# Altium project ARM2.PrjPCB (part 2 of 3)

## Sheet P07_DDR3_SDRAM.SchDoc
size A3
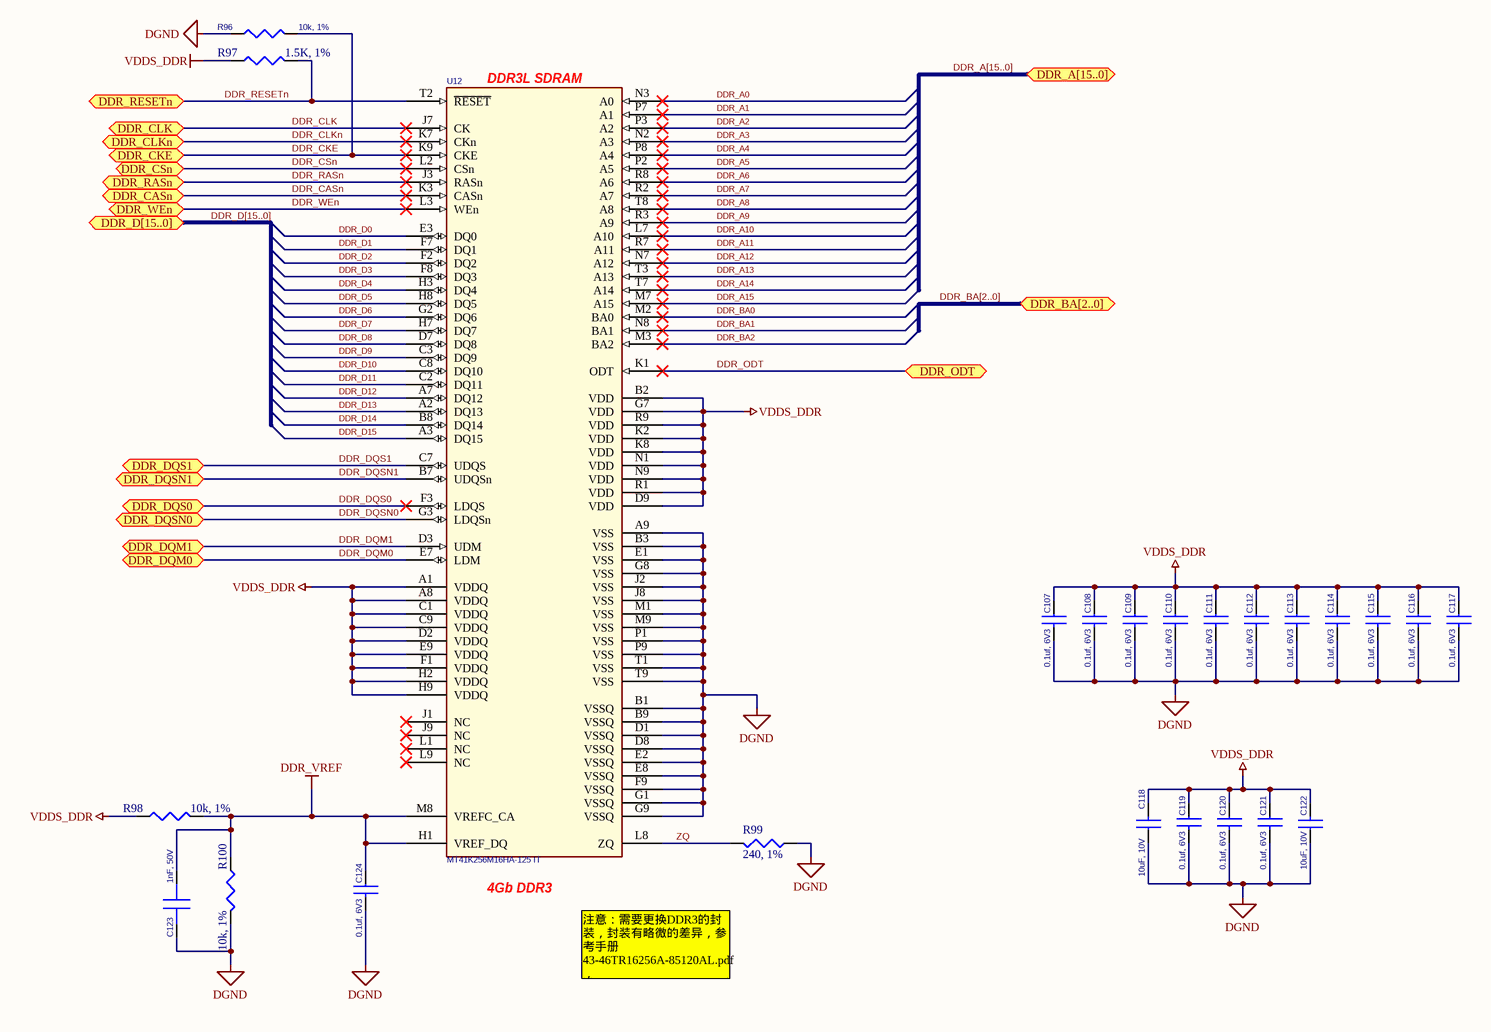
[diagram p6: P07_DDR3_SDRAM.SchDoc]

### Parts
C107  0.1uf, 6V3  [402]
C108  0.1uf, 6V3  [402]
C109  0.1uf, 6V3  [402]
C110  0.1uf, 6V3  [402]
C111  0.1uf, 6V3  [402]
C112  0.1uf, 6V3  [402]
C113  0.1uf, 6V3  [402]
C114  0.1uf, 6V3  [402]
C115  0.1uf, 6V3  [402]
C116  0.1uf, 6V3  [402]
C117  0.1uf, 6V3  [402]
C118  10uF, 10V  [805]
C119  0.1uf, 6V3  [402]
C120  0.1uf, 6V3  [402]
C121  0.1uf, 6V3  [402]
C122  10uF, 10V  [805]
C123  1nF, 50V  [402]
C124  0.1uf, 6V3  [402]
R96  10k, 1%  [R0402]
R97  1.5K, 1%  [R0402]
R98  10k, 1%  [R0402]
R99  240, 1%  [R0402]
R100  10k, 1%  [R0402]
U12  MT41K256M16HA-125 IT  [IS43TR16256A-15HBLI/MT41K256M16HA-125 IT_E TR]

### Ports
DDR_A[15..0], DDR_BA[2..0], DDR_CASn, DDR_CKE, DDR_CLK, DDR_CLKn, DDR_CSn, DDR_D[15..0], DDR_DQM0, DDR_DQM1, DDR_DQS0, DDR_DQS1, DDR_DQSN0, DDR_DQSN1, DDR_ODT, DDR_RASn, DDR_RESETn, DDR_WEn

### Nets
DDR_VREF: C123.1 C124.1 R98.2 R100.1 U12.H1(VREF_DQ) U12.M8(VREFC_CA)
DGND: C107.2 C108.2 C109.2 C110.2 C111.2 C112.2 C113.2 C114.2 C115.2 C116.2 C117.2 C118.1 C119.2 C120.2 C121.2 C122.1 C123.2 C124.2 R96.1 R99.1 R100.2 U12.A9(VSS) U12.B1(VSSQ) U12.B3(VSS) U12.B9(VSSQ) U12.D1(VSSQ) U12.D8(VSSQ) U12.E1(VSS) U12.E2(VSSQ) U12.E8(VSSQ) U12.F9(VSSQ) U12.G1(VSSQ) U12.G8(VSS) U12.G9(VSSQ) U12.J2(VSS) U12.J8(VSS) U12.M1(VSS) U12.M9(VSS) U12.P1(VSS) U12.P9(VSS) U12.T1(VSS) U12.T9(VSS)
VDDS_DDR: C107.1 C108.1 C109.1 C110.1 C111.1 C112.1 C113.1 C114.1 C115.1 C116.1 C117.1 C118.2 C119.1 C120.1 C121.1 C122.2 R97.1 R98.1 U12.A1(VDDQ) U12.A8(VDDQ) U12.B2(VDD) U12.C1(VDDQ) U12.C9(VDDQ) U12.D2(VDDQ) U12.D9(VDD) U12.E9(VDDQ) U12.F1(VDDQ) U12.G7(VDD) U12.H2(VDDQ) U12.H9(VDDQ) U12.K2(VDD) U12.K8(VDD) U12.N1(VDD) U12.N9(VDD) U12.R1(VDD) U12.R9(VDD)
DDR_A0: U12.N3(A0)
DDR_A1: U12.P7(A1)
DDR_A2: U12.P3(A2)
DDR_A3: U12.N2(A3)
DDR_A4: U12.P8(A4)
DDR_A5: U12.P2(A5)
DDR_A6: U12.R8(A6)
DDR_A7: U12.R2(A7)
DDR_A8: U12.T8(A8)
DDR_A9: U12.R3(A9)
DDR_A10: U12.L7(A10)
DDR_A11: U12.R7(A11)
DDR_A12: U12.N7(A12)
DDR_A13: U12.T3(A13)
DDR_A14: U12.T7(A14)
DDR_A15: U12.M7(A15)
DDR_BA0: U12.M2(BA0)
DDR_BA1: U12.N8(BA1)
DDR_BA2: U12.M3(BA2)
DDR_CASn: U12.K3(CASn) ; port DDR_CASn
DDR_CKE: R96.2 U12.K9(CKE) ; port DDR_CKE
DDR_CLK: U12.J7(CK) ; port DDR_CLK
DDR_CLKn: U12.K7(CKn) ; port DDR_CLKn
DDR_CSn: U12.L2(CSn) ; port DDR_CSn
DDR_D0: U12.E3(DQ0)
DDR_D1: U12.F7(DQ1)
DDR_D2: U12.F2(DQ2)
DDR_D3: U12.F8(DQ3)
DDR_D4: U12.H3(DQ4)
DDR_D5: U12.H8(DQ5)
DDR_D6: U12.G2(DQ6)
DDR_D7: U12.H7(DQ7)
DDR_D8: U12.D7(DQ8)
DDR_D9: U12.C3(DQ9)
DDR_D10: U12.C8(DQ10)
DDR_D11: U12.C2(DQ11)
DDR_D12: U12.A7(DQ12)
DDR_D13: U12.A2(DQ13)
DDR_D14: U12.B8(DQ14)
DDR_D15: U12.A3(DQ15)
DDR_DQM0: U12.E7(LDM) ; port DDR_DQM0
DDR_DQM1: U12.D3(UDM) ; port DDR_DQM1
DDR_DQS0: U12.F3(LDQS) ; port DDR_DQS0
DDR_DQS1: U12.C7(UDQS) ; port DDR_DQS1
DDR_DQSN0: U12.G3(LDQSn) ; port DDR_DQSN0
DDR_DQSN1: U12.B7(UDQSn) ; port DDR_DQSN1
DDR_ODT: U12.K1(ODT) ; port DDR_ODT
DDR_RASn: U12.J3(RASn) ; port DDR_RASn
DDR_RESETn: R97.2 U12.T2(~{RESET}) ; port DDR_RESETn
DDR_WEn: U12.L3(WEn) ; port DDR_WEn
ZQ: R99.2 U12.L8(ZQ)

Not connected (* = marked no-connect by the designer): U12 J1(NC)* J9(NC)* L1(NC)* L9(NC)*

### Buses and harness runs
bus DDR_A[15..0] = port DDR_A[15..0]
bus DDR_BA[2..0] = port DDR_BA[2..0]
bus DDR_D[15..0] = port DDR_D[15..0]

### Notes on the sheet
- (near U12) DDR3L SDRAM
- (near U12) 4Gb DDR3
- 注意：需要更换DDR3的封装，封装有略微的差异，参考手册43-46TR16256A-85120AL.pdf，
  96-ball FBGA (9mm*13mm)

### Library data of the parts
C107-C117 C119-C121 C124 = CAP_0.01uf_X7R_16V_10%_0402: CAP CER 0.1UF 6.3V 10% X5R 0402; Manufacturer: TDK Corporation; Manufacturer Part Number: C1005X5R0J104K050BA; Capacitance: 0.1µF; Tolerance: ?0%
C118 C122 = CAP_4.7uF_X5R_6.3V_10%_0603: CAP CER 10UF 10V Y5V 0805; Manufacturer: TDK Corporation; Manufacturer Part Number: C2012Y5V1A106Z; Capacitance: 10µF; Tolerance: -20%, +80%; Temperature Coefficient: Y5V (F)
C123 = CAP SMD: CAP CER 1000PF 16V 10% X7R 0402; Manufacturer: Yageo; Manufacturer Part Number: CC0402KRX7R7BB102; Tolerance: ?0%
R96 R98 R100 = RES_10K_1/16W_1%_0402: RES 10K OHM 1/16W 5% 0402 SMD; Manufacturer: Rohm Semiconductor; Manufacturer Part Number: MCR01MZPJ103; Power (Watts): 0.063W, 1/16W; Temperature Coefficient: ?00ppm/°C; Tolerance: ?%
R97 = RES_10K_1/16W_1%_0402: RES 1.50K OHM 1/16W 1% 0402 SMD; Manufacturer: Yageo; Manufacturer Part Number: RC0402FR-071K5L; Power (Watts): 0.063W, 1/16W; Temperature Coefficient: ?00ppm/°C; Tolerance: ?%
R99 = RES_10K_1/16W_1%_0402: RES 240 OHM 1/10W 5% 0402 SMD; Manufacturer: Yageo; Manufacturer Part Number: RC0402FR-07240RL; Resistance (Ohms): 240; Power (Watts): 0.063W, 1/16W; Temperature Coefficient: ?00ppm/°C; Tolerance: ?%
U12 = MT41K256M16HA: DDR2 SDRAM 2Gb (256Mx8); Manufacturer: ISSI; Manufacturer Part Number: IS43TR16256A-15HBLI; Lead Time: 0 weeks

## Sheet P08_NandFlash.SchDoc
size A4
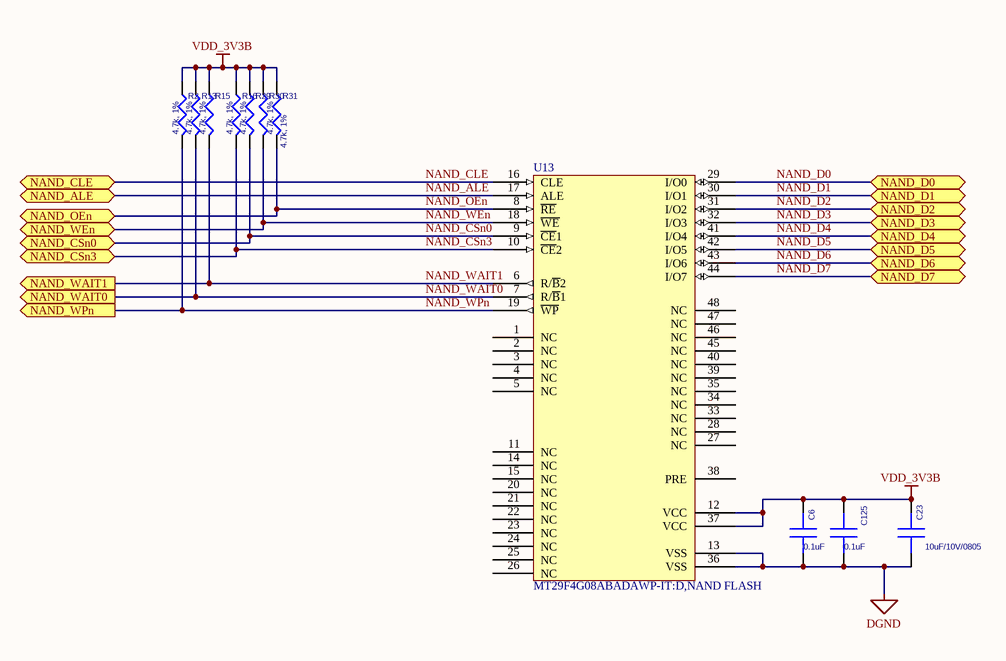
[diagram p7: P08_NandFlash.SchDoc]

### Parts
C6  0.1uF  [402]
C23  10uF/10V/0805  [3528T/CASE B]
C125  0.1uF  [402]
R2  4.7k, 1%  [R0402]
R13  4.7k, 1%  [R0402]
R15  4.7k, 1%  [R0402]
R16  4.7k, 1%  [R0402]
R29  4.7k, 1%  [R0402]
R30  4.7k, 1%  [R0402]
R31  4.7k, 1%  [R0402]
U13  MT29F4G08ABADAWP-IT:D,NAND FLASH  [MT29F4G08ABADAWP-ITD]

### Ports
NAND_ALE (bidir), NAND_CLE (bidir), NAND_CSn0 (bidir), NAND_CSn3 (bidir), NAND_D0 (bidir), NAND_D1 (bidir), NAND_D2 (bidir), NAND_D3 (bidir), NAND_D4 (bidir), NAND_D5 (bidir), NAND_D6 (bidir), NAND_D7 (bidir), NAND_OEn (bidir), NAND_WAIT0 (out), NAND_WAIT1 (out), NAND_WEn (bidir), NAND_WPn (out)

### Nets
DGND: C6.2 C23.2 C125.2 U13.13(VSS) U13.36(VSS)
VDD_3V3B: C6.1 C23.1 C125.1 R2.2(P2) R13.2(P2) R15.2(P2) R16.2(P2) R29.2(P2) R30.2(P2) R31.2(P2) U13.12(VCC) U13.37(VCC)
NAND_ALE: U13.17(ALE) ; port NAND_ALE
NAND_CLE: U13.16(CLE) ; port NAND_CLE
NAND_CSn0: R29.1(P1) U13.9(~{CE}1) ; port NAND_CSn0
NAND_CSn3: R16.1(P1) U13.10(~{CE}2) ; port NAND_CSn3
NAND_D0: U13.29(I/O0) ; port NAND_D0
NAND_D1: U13.30(I/O1) ; port NAND_D1
NAND_D2: U13.31(I/O2) ; port NAND_D2
NAND_D3: U13.32(I/O3) ; port NAND_D3
NAND_D4: U13.41(I/O4) ; port NAND_D4
NAND_D5: U13.42(I/O5) ; port NAND_D5
NAND_D6: U13.43(I/O6) ; port NAND_D6
NAND_D7: U13.44(I/O7) ; port NAND_D7
NAND_OEn: R31.1(P1) U13.8(~{RE}) ; port NAND_OEn
NAND_WAIT0: R13.1(P1) U13.7(R/~{B}1) ; port NAND_WAIT0
NAND_WAIT1: R15.1(P1) U13.6(R/~{B}2) ; port NAND_WAIT1
NAND_WEn: R30.1(P1) U13.18(~{WE}) ; port NAND_WEn
NAND_WPn: R2.1(P1) U13.19(~{WP}) ; port NAND_WPn

Not connected (* = marked no-connect by the designer): U13 1(NC) 2(NC) 3(NC) 4(NC) 5(NC) 11(NC) 14(NC) 15(NC) 20(NC) 21(NC) 22(NC) 23(NC) 24(NC) 25(NC) 26(NC) 27(NC) 28(NC) 33(NC) 34(NC) 35(NC) 38(PRE) 39(NC) 40(NC) 45(NC) 46(NC) 47(NC) 48(NC)

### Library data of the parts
C6 C23 C125 = CAP SMD: No Description
R2 R13 R15 R16 R29-R31 = RES SMD: RES 10K OHM 1/16W 5% 0402 SMD; Manufacturer: Rohm Semiconductor; Manufacturer Part Number: MCR01MZPJ103; Power (Watts): 0.063W, 1/16W; Temperature Coefficient: ?00ppm/°C; Tolerance: ?%
U13 = MT29F4G08ABADAWP-IT:D

## Sheet P09_Ethernet.SchDoc
size A2
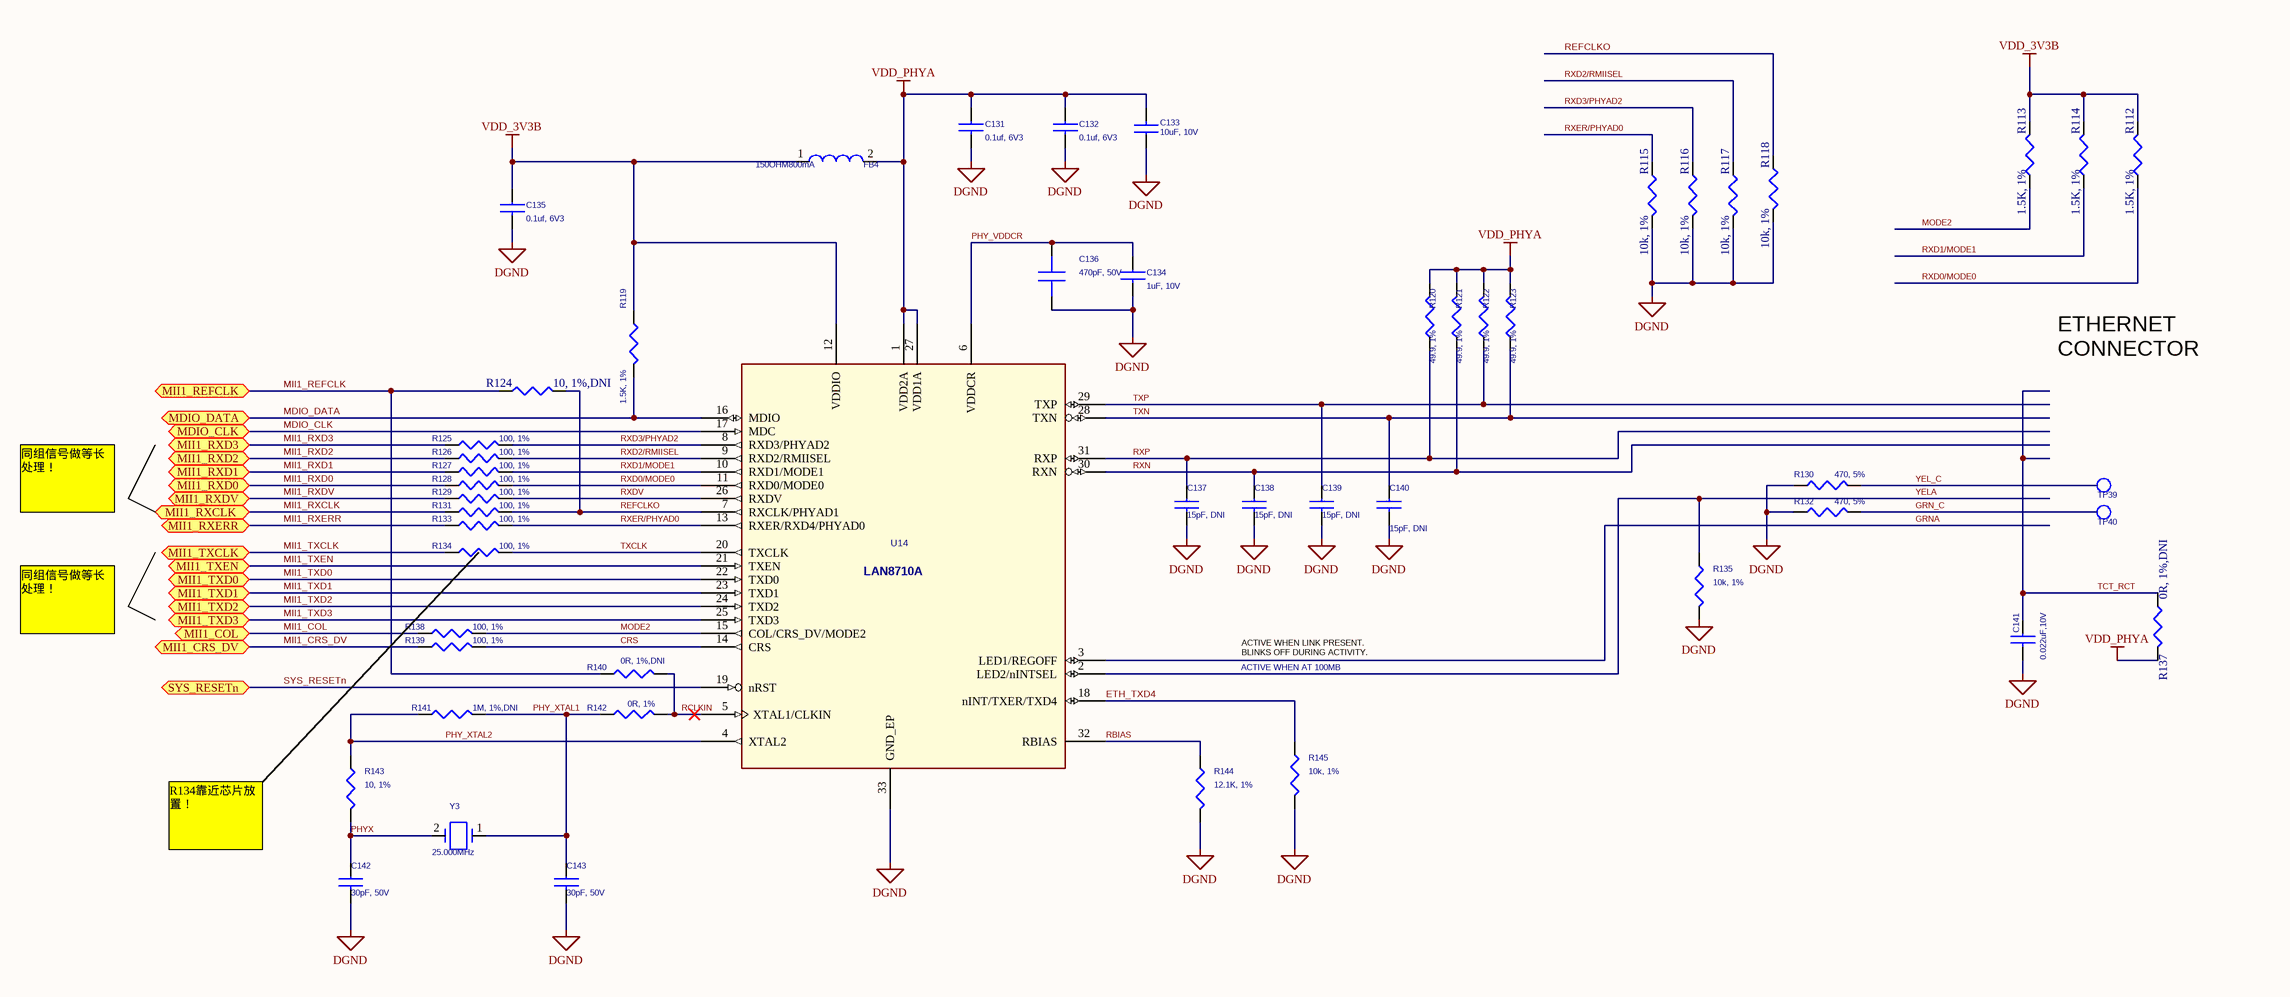
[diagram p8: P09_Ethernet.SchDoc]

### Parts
C131  0.1uf, 6V3  [402]
C132  0.1uf, 6V3  [402]
C133  10uF, 10V  [805]
C134  1uF, 10V  [402]
C135  0.1uf, 6V3  [402]
C136  470pF, 50V  [402]
C137  15pF, DNI  [402]
C138  15pF, DNI  [402]
C139  15pF, DNI  [402]
C140  15pF, DNI  [402]
C141  0.022uF,10V  [402]
C142  30pF, 50V  [402]
C143  30pF, 50V  [402]
FB4  150OHM800mA  [SM-7351-IND-0805]
R112  1.5K, 1%  [R0402]
R113  1.5K, 1%  [R0402]
R114  1.5K, 1%  [R0402]
R115  10k, 1%  [R0402]
R116  10k, 1%  [R0402]
R117  10k, 1%  [R0402]
R118  10k, 1%  [R0402]
R119  1.5K, 1%  [R0402]
R120  49.9, 1%  [R0402]
R121  49.9, 1%  [R0402]
R122  49.9, 1%  [R0402]
R123  49.9, 1%  [R0402]
R124  10, 1%,DNI  [R0402]
R125  100, 1%  [R0402]
R126  100, 1%  [R0402]
R127  100, 1%  [R0402]
R128  100, 1%  [R0402]
R129  100, 1%  [R0402]
R130  470, 5%  [R0402]
R131  100, 1%  [R0402]
R132  470, 5%  [R0402]
R133  100, 1%  [R0402]
R134  100, 1%  [R0402]
R135  10k, 1%  [R0402]
R137  0R, 1%,DNI  [R0402]
R138  100, 1%  [R0402]
R139  100, 1%  [R0402]
R140  0R, 1%,DNI  [R0402]
R141  1M, 1%,DNI  [R0402]
R142  0R, 1%  [R0402]
R143  10, 1%  [R0402]
R144  12.1K, 1%  [R0402]
R145  10k, 1%  [R0402]
TP39  TESTPT1  [tp1-8040]  (value not drawn)  (no BOM)
TP40  TESTPT1  [tp1-8040]  (value not drawn)  (no BOM)
U14  LAN8710A  [QFN32_5X5MM_EP3P3MM/LAN8710Ai-EZK/QFN-32]
Y3  25.000MHz  [XTAL150SMD_125X196]

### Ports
MDIO_CLK, MDIO_DATA, MII1_COL, MII1_CRS_DV, MII1_REFCLK, MII1_RXCLK, MII1_RXD0, MII1_RXD1, MII1_RXD2, MII1_RXD3, MII1_RXDV, MII1_RXERR, MII1_TXCLK, MII1_TXD0, MII1_TXD1, MII1_TXD2, MII1_TXD3, MII1_TXEN, SYS_RESETn

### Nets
DGND: C131.2 C132.2 C133.1 C134.2 C135.2 C136.2 C137.2 C138.2 C139.2 C140.2 C141.2 C142.2 C143.2 R115.2 R116.2 R117.2 R118.2 R130.1 R132.1 R135.2 R144.2 R145.2 U14.33(GND_EP)
VDD_3V3B: C135.1 FB4.1 R112.2 R113.2 R114.2 R119.1 U14.12(VDDIO)
VDD_PHYA: C131.1 C132.1 C133.2 FB4.2 R120.2 R121.2 R122.2 R123.2 R137.2 U14.1(VDD2A) U14.27(VDD1A)
CRS: R139.2 U14.14(CRS)
ETH_TXD4: R145.1 U14.18(nINT/TXER/TXD4)
GRN_C: R132.2 TP40.1(TP)
GRNA: U14.3(LED1/REGOFF)
MDIO_CLK: U14.17(MDC) ; port MDIO_CLK
MDIO_DATA: R119.2 U14.16(MDIO) ; port MDIO_DATA
MII1_COL: R138.1 ; port MII1_COL
MII1_CRS_DV: R139.1 ; port MII1_CRS_DV
MII1_REFCLK: R124.1 R140.1 ; port MII1_REFCLK
MII1_RXCLK: R131.1 ; port MII1_RXCLK
MII1_RXD0: R128.1 ; port MII1_RXD0
MII1_RXD1: R127.1 ; port MII1_RXD1
MII1_RXD2: R126.1 ; port MII1_RXD2
MII1_RXD3: R125.1 ; port MII1_RXD3
MII1_RXDV: R129.1 ; port MII1_RXDV
MII1_RXERR: R133.1 ; port MII1_RXERR
MII1_TXCLK: R134.1 ; port MII1_TXCLK
MII1_TXD0: U14.22(TXD0) ; port MII1_TXD0
MII1_TXD1: U14.23(TXD1) ; port MII1_TXD1
MII1_TXD2: U14.24(TXD2) ; port MII1_TXD2
MII1_TXD3: U14.25(TXD3) ; port MII1_TXD3
MII1_TXEN: U14.21(TXEN) ; port MII1_TXEN
MODE2: R113.1 R138.2 U14.15(COL/CRS_DV/MODE2)
PHY_VDDCR: C134.1 C136.1 U14.6(VDDCR)
PHY_XTAL1: C143.1 R141.2 R142.1 Y3.1
PHY_XTAL2: R141.1 R143.1 U14.4(XTAL2)
PHYX: C142.1 R143.2 Y3.2
RBIAS: R144.1 U14.32(RBIAS)
RCLKIN: R140.2 R142.2 U14.5(XTAL1/CLKIN)
REFCLKO: R118.1 R124.2 R131.2 U14.7(RXCLK/PHYAD1)
RXD0/MODE0: R112.1 R128.2 U14.11(RXD0/MODE0)
RXD1/MODE1: R114.1 R127.2 U14.10(RXD1/MODE1)
RXD2/RMIISEL: R117.1 R126.2 U14.9(RXD2/RMIISEL)
RXD3/PHYAD2: R116.1 R125.2 U14.8(RXD3/PHYAD2)
RXDV: R129.2 U14.26(RXDV)
RXER/PHYAD0: R115.1 R133.2 U14.13(RXER/RXD4/PHYAD0)
RXN: C138.1 R121.1 U14.30(RXN)
RXP: C137.1 R120.1 U14.31(RXP)
SYS_RESETn: U14.19(nRST) ; port SYS_RESETn
TCT_RCT: C141.1 R137.1
TXCLK: R134.2 U14.20(TXCLK)
TXN: C140.1 R123.1 U14.28(TXN)
TXP: C139.1 R122.1 U14.29(TXP)
YEL_C: R130.2 TP39.1(TP)
YELA: R135.1 U14.2(LED2/nINTSEL)

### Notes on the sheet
- ETHERNET
  CONNECTOR
- 同组信号做等长处理！
- ACTIVE WHEN LINK PRESENT.
  BLINKS OFF DURING ACTIVITY.
- ACTIVE WHEN AT 100MB
- R134靠近芯片放置！

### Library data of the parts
C131 C132 C135 = CAP_0.1uF_X7R_16V_10% 0402: CAP CER 0.1UF 6.3V 10% X5R 0402; Manufacturer: TDK Corporation; Manufacturer Part Number: C1005X5R0J104K050BA; Capacitance: 0.1µF; Tolerance: ?0%
C133 = CAP_4.7uF_X5R_6.3V_10%_0603: as C118 on sheet P07_DDR3_SDRAM
C134 = CAP_1.0UF_X5R_10V_10%_0402: CAP CER 1UF 10V 10% X5R 0402; Manufacturer: AVX Corporation; Manufacturer Part Number: 0402ZD105KAT2A; Capacitance: 1.0µF; Tolerance: ?0%
C136 = 470pF/5%/50V/C0G/0603_0: CAP CER 470PF 50V 10% X7R 0402; Manufacturer: Murata Electronics North America; Manufacturer Part Number: GRM155R71H471KA01D; Tolerance: ?0%
C137-C140 = CAP_0402_100pF_COG_50V: CAP CER 15PF 50V 5% NP0 0402; Manufacturer: TDK Corporation; Manufacturer Part Number: C1005C0G1H150J050BA; Tolerance: ?%; Temperature Coefficient: C0G, NP0
C141 = CAP_0402_0.1uf_X5R_10V: CAP CER 0.022UF 10V 10% X7R 0402; Manufacturer: Taiyo Yuden; Manufacturer Part Number: LMK105B7223KV-F; Capacitance: 0.022µF; Tolerance: ?0%
C142 C143 = CAP_30PF_COG_50V_5%_0402: CAP CER 30PF 50V 5% NP0 0402; Manufacturer: TDK Corporation; Manufacturer Part Number: C1005C0G1H300J; Tolerance: ?%; Temperature Coefficient: C0G, NP0
FB4 = FER_180_200_0: FERRITE 800MA 150 OHM 0805 SMD; PartName: FerriteBead150ohm800mA; Mfr: Steward; MfrNum: LI0805H151R-10; TIIntPartnumber: 1L0010; Manufacturer: Laird-Signal Integrity Products; Vendor: Digikey; DC Resistance (DCR): 150 mOhm Max; Filter Type: Differential Mode - Single; Impedance @ Frequency: 150 Ohm @ 100MHz
R112-R114 = RES_10K_1/16W_1%_0402: as R97 on sheet P07_DDR3_SDRAM
R115-R118 R135 R145 = RES_10K_1/16W_1%_0402: as R96 on sheet P07_DDR3_SDRAM
R119 = RES_1.5K_1/16W_5%_0402: RES 1.50K OHM 1/16W 1% 0402 SMD; Manufacturer: Yageo; Manufacturer Part Number: RC0402FR-071K5L; Power (Watts): 0.063W, 1/16W; Temperature Coefficient: ?00ppm/°C; Tolerance: ?%
R120-R123 = RES_4.7K_0402: RES 49.9 OHM 1/16W 1% 0402 SMD; Manufacturer: Yageo; Manufacturer Part Number: RC0402FR-0749R9L; Power (Watts): 0.063W, 1/16W; Resistance (Ohms): 49.9; Temperature Coefficient: ?00ppm/°C; Tolerance: ?%
R124 = RES_10K_1/16W_1%_0402: Resistor 10Kohm 1/16W 1% 0402; Manufacturer: Stackpole Electronics Inc; Manufacturer Part Number: RMCF0402FT10R0; Power (Watts): 0.063W, 1/16W; Resistance (Ohms): 10; Temperature Coefficient: ?00ppm/°C; Tolerance: ?%
R125 R126 R129 R134 R138 = 100-1/10W-1%-0603_4: RES 100 OHM 1/10W 5% 0402 SMD; PART#: Rohm MCR03EZPFX1000; Manufacturer: Panasonic Electronic Components; Manufacturer Part Number: ERJ-2RKF1000X; Resistance (Ohms): 100; Power (Watts): 0.1W, 1/10W; Temperature Coefficient: ?00ppm/°C
R127 R128 R131 R133 R139 = RES_100_1/10W_5%_0402: RES 100 OHM 1/10W 5% 0402 SMD; Manufacturer: Panasonic Electronic Components; Manufacturer Part Number: ERJ-2RKF1000X; Resistance (Ohms): 100; Power (Watts): 0.1W, 1/10W; Temperature Coefficient: ?00ppm/°C; Tolerance: ?%
R130 R132 = RES_470_1/10W_5%_0402: RES 470 OHM 1/10W 5% 0402 SMD; Manufacturer: Panasonic Electronic Components; Manufacturer Part Number: ERJ-2GEJ471X; Resistance (Ohms): 470; Power (Watts): 0.1W, 1/10W; Temperature Coefficient: ?00ppm/°C; Tolerance: ?%
R137 R140 R142 = RES_0_1/16W_1%_0402: RES 0.0 OHM 1/16W 0402 SMD; Manufacturer: Yageo; Manufacturer Part Number: RC0402JR-070RL; Power (Watts): 0.063W, 1/16W; Resistance (Ohms): 0.0; Tolerance: Jumper
R141 = RES_1M_1/16W_1%_0402: RES 1M OHM 1/16W 1% 0402 SMD; Manufacturer: Stackpole Electronics Inc; Manufacturer Part Number: RMCF0402FT1M00; Power (Watts): 0.063W, 1/16W; Temperature Coefficient: ?00ppm/°C; Tolerance: ?%
R143 = RES_10K_1/16W_1%_0402: RES 10 OHM 1/16W 1% 0402 SMD; Manufacturer: Stackpole Electronics Inc; Manufacturer Part Number: RMCF0402FT10R0; Resistance (Ohms): 10; Power (Watts): 0.063W, 1/16W; Temperature Coefficient: ?00ppm/°C; Tolerance: ?%
R144 = RES_12.1K_1/16W_1%_0402: RES 12.1K OHM 1/16W 1% 0402 SMD; Manufacturer: Yageo; Manufacturer Part Number: RC0402FR-0712K1L; Power (Watts): 0.063W, 1/16W; Temperature Coefficient: ?00ppm/°C; Tolerance: ?%
U14 = LAN8710 QFN32_1: Ethernet ICs 10/100 Ethernet XCVR w/HPAutoMDIX FlexPwr; PART#: SMSC LAN8710A-EZK; Manufacturer: Microchip Technology; Manufacturer Part Number: LAN8710A-EZK-TR; Data Rate: 125 Mb/s; Number of Transceivers: 1; Standard Supported: 802.3, 802.3u; Supply Voltage - Max: 3.6 V; Supply Voltage - Min: 1.6 V, 3 V
Y3 = Suntsu ITEMP 25MHz _0.005% 20pf: Manufacturer: Abracon Corporation; Manufacturer Part Number: ABM3-25.000MHZ-B2-T; Frequency: 25MHz; Frequency Stability: ?0ppm; Load Capacitance: 18pF; ESR (Equivalent Series Resistance): 50 Ohm; Operating Mode: Fundamental

## Sheet P10_LCD.SchDoc
size A1
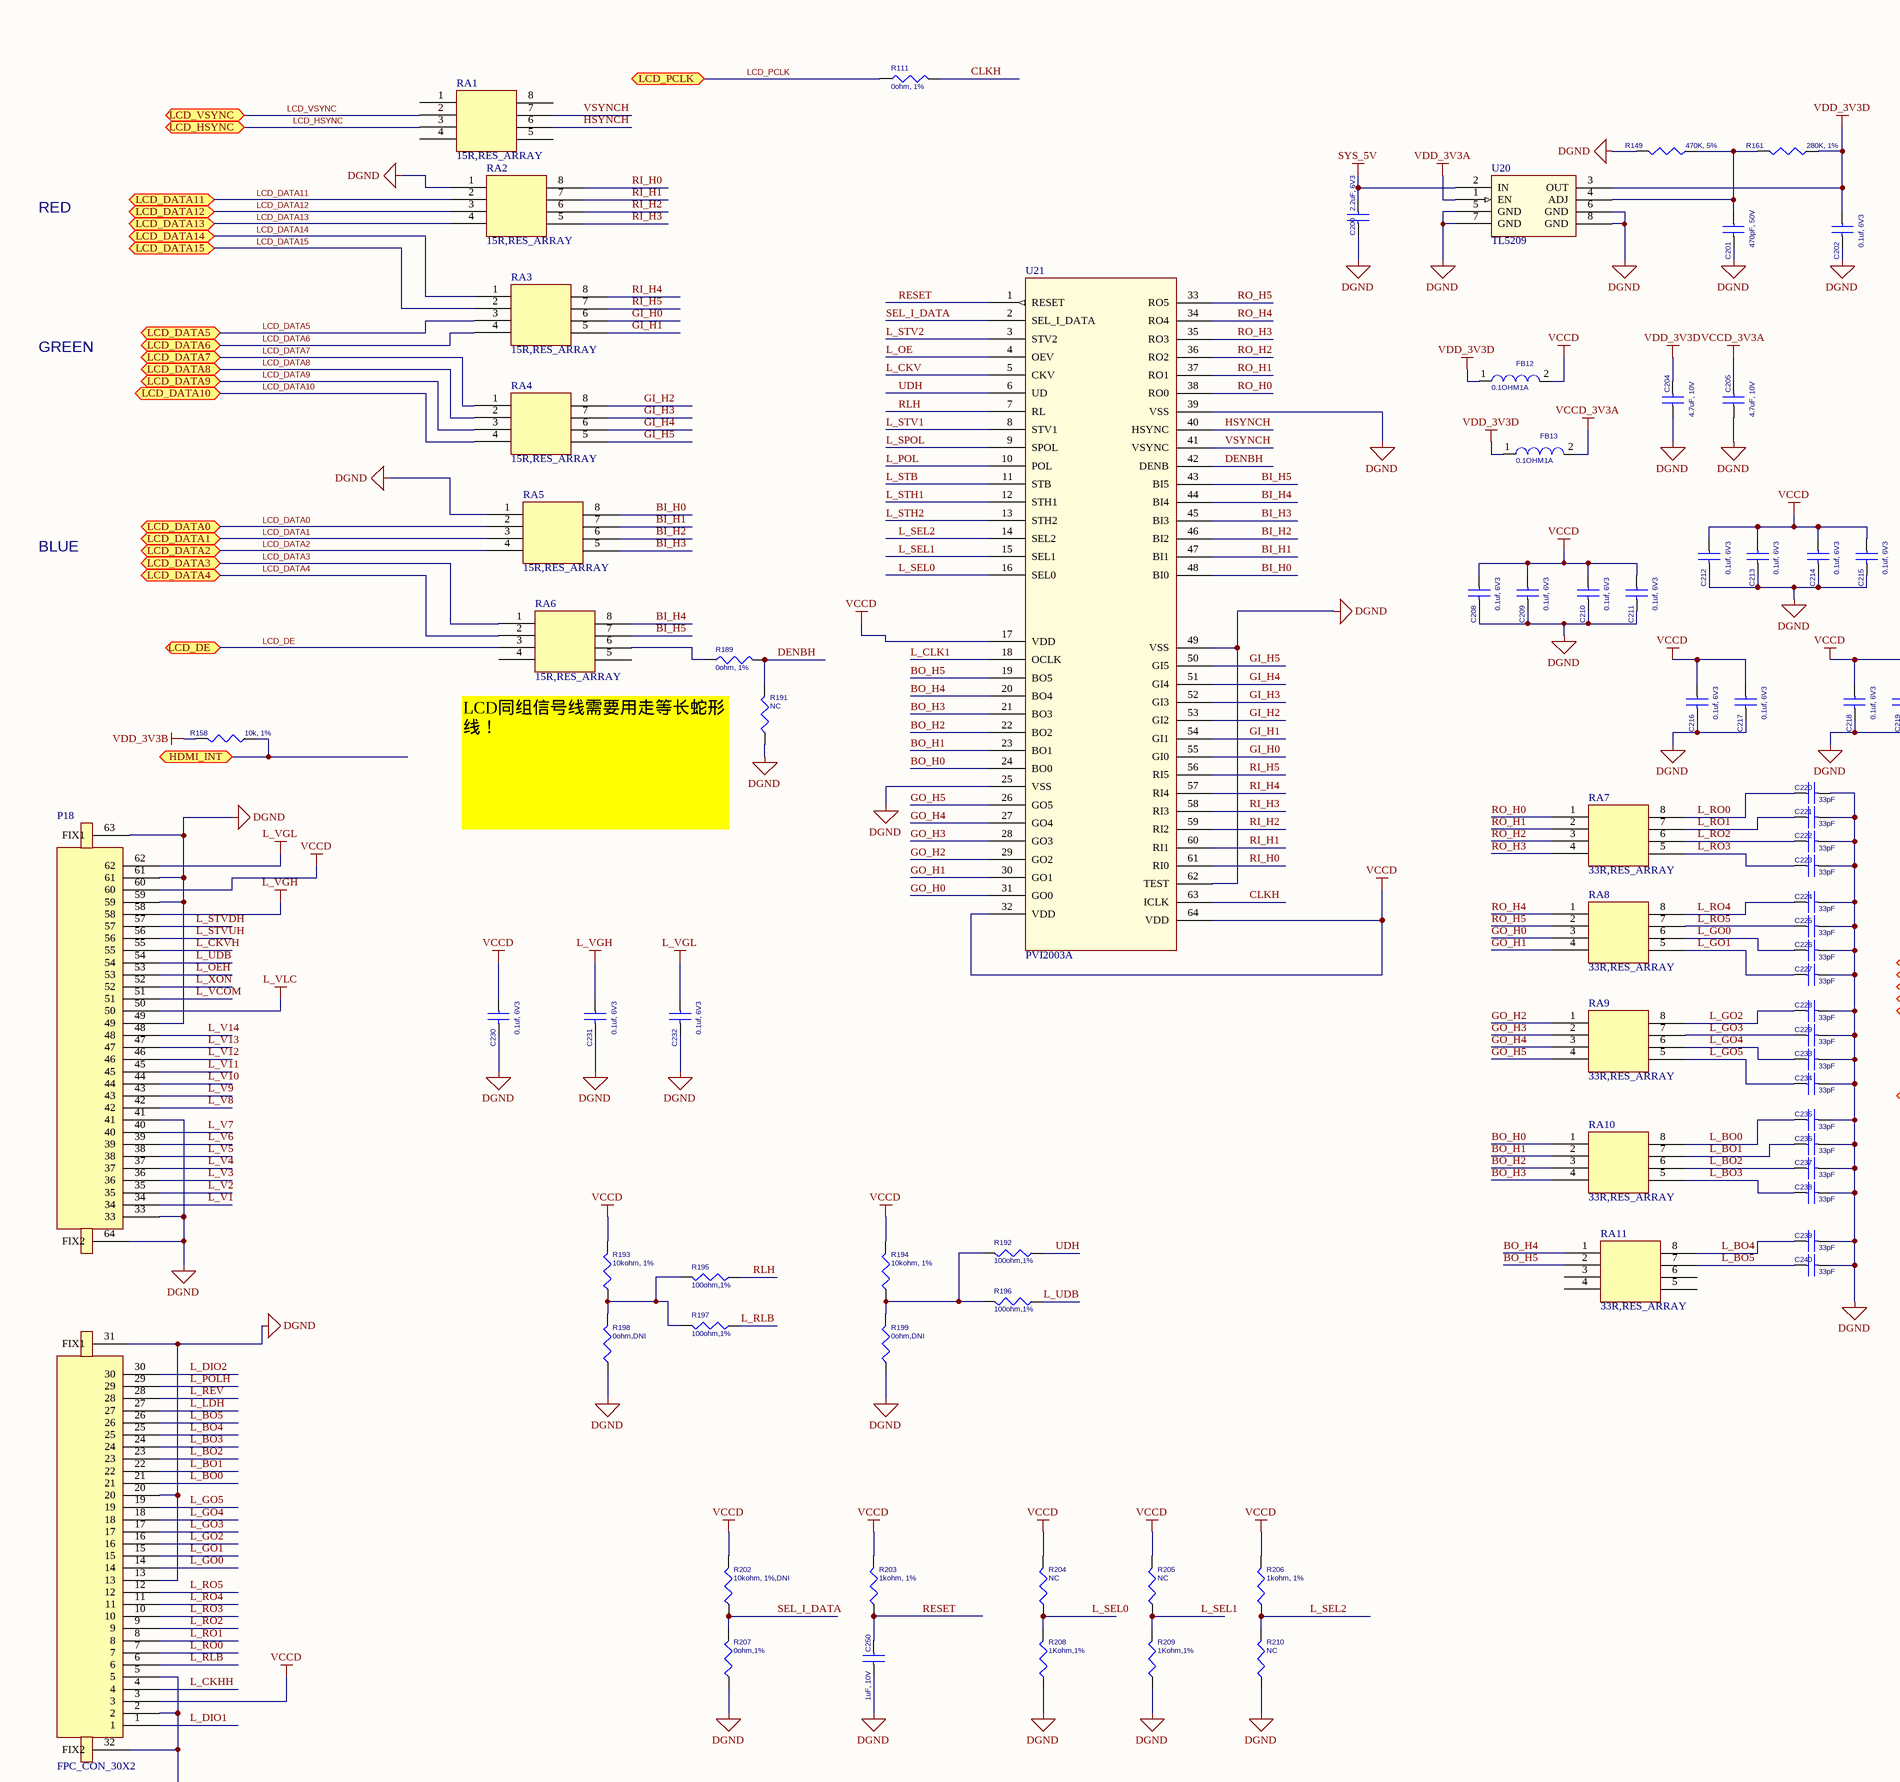
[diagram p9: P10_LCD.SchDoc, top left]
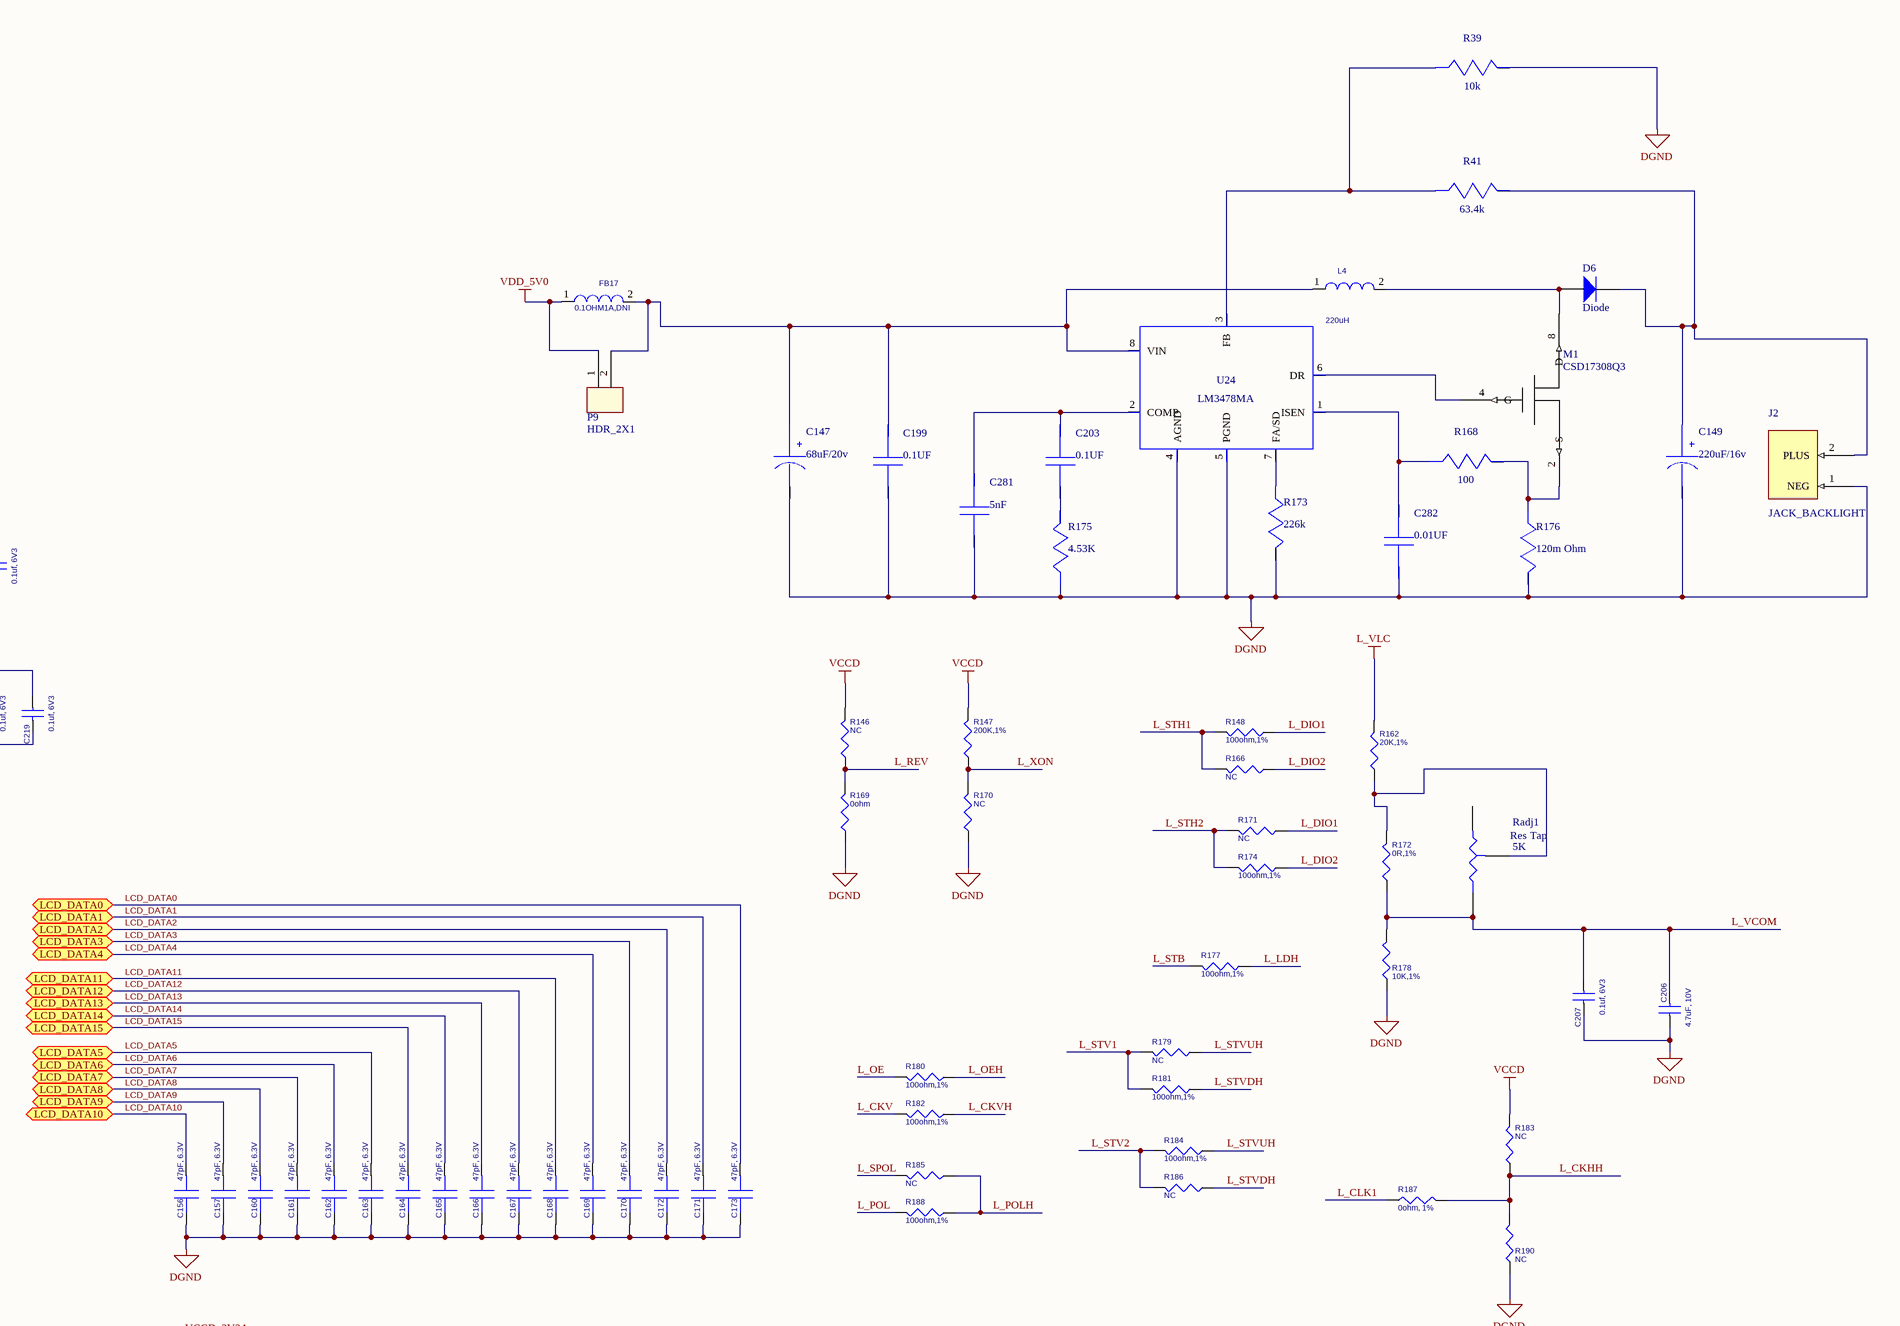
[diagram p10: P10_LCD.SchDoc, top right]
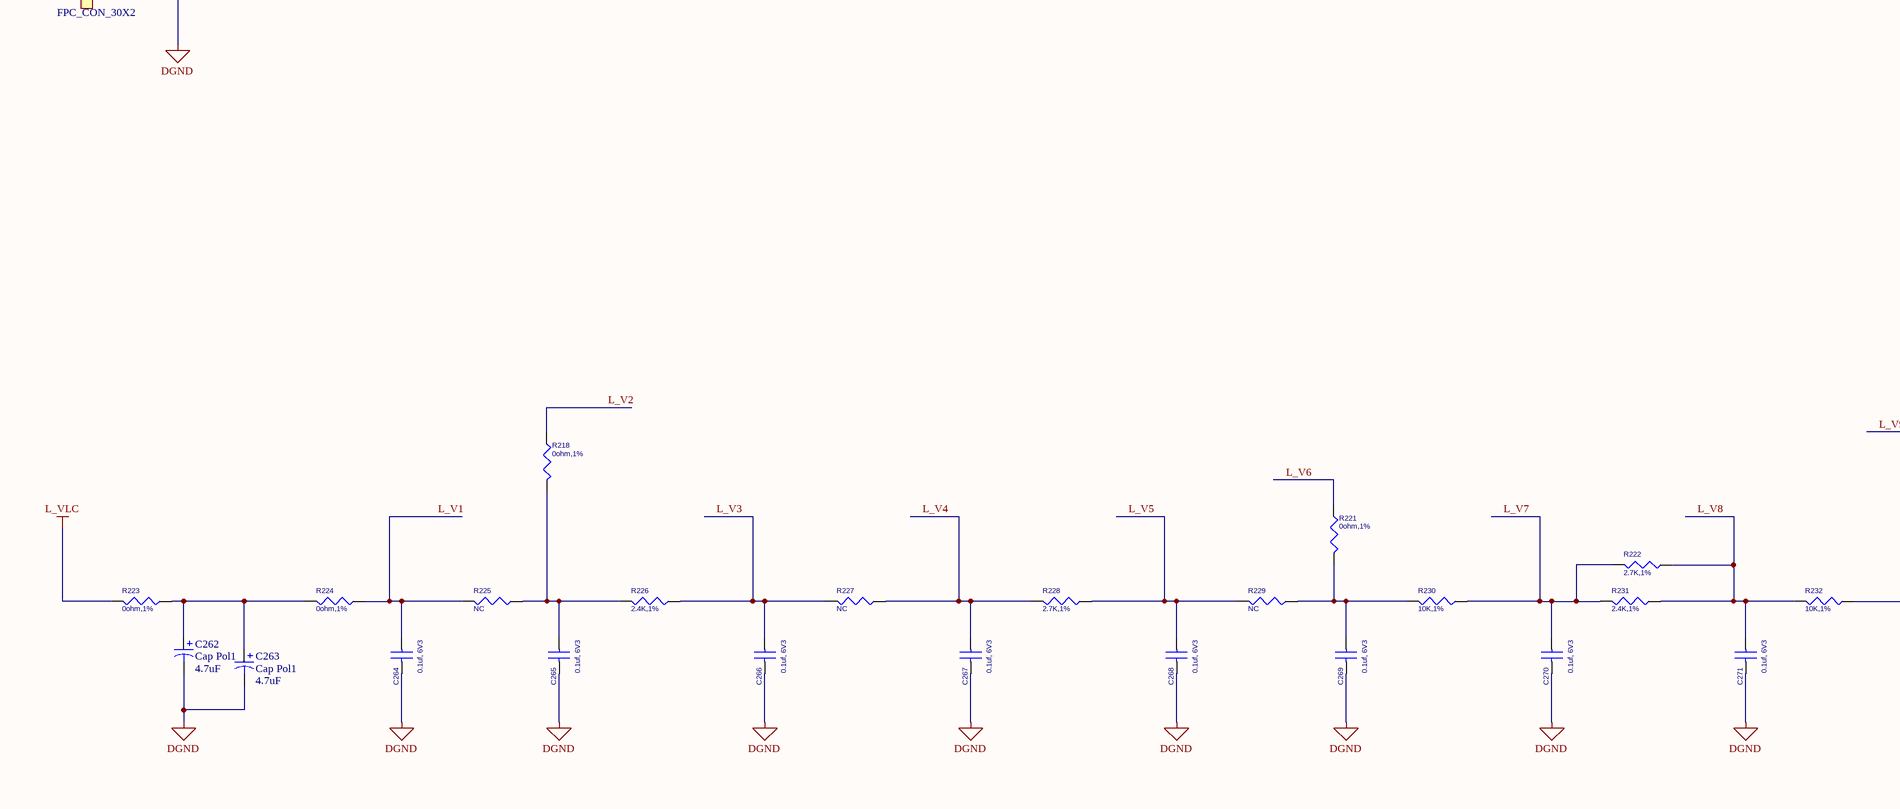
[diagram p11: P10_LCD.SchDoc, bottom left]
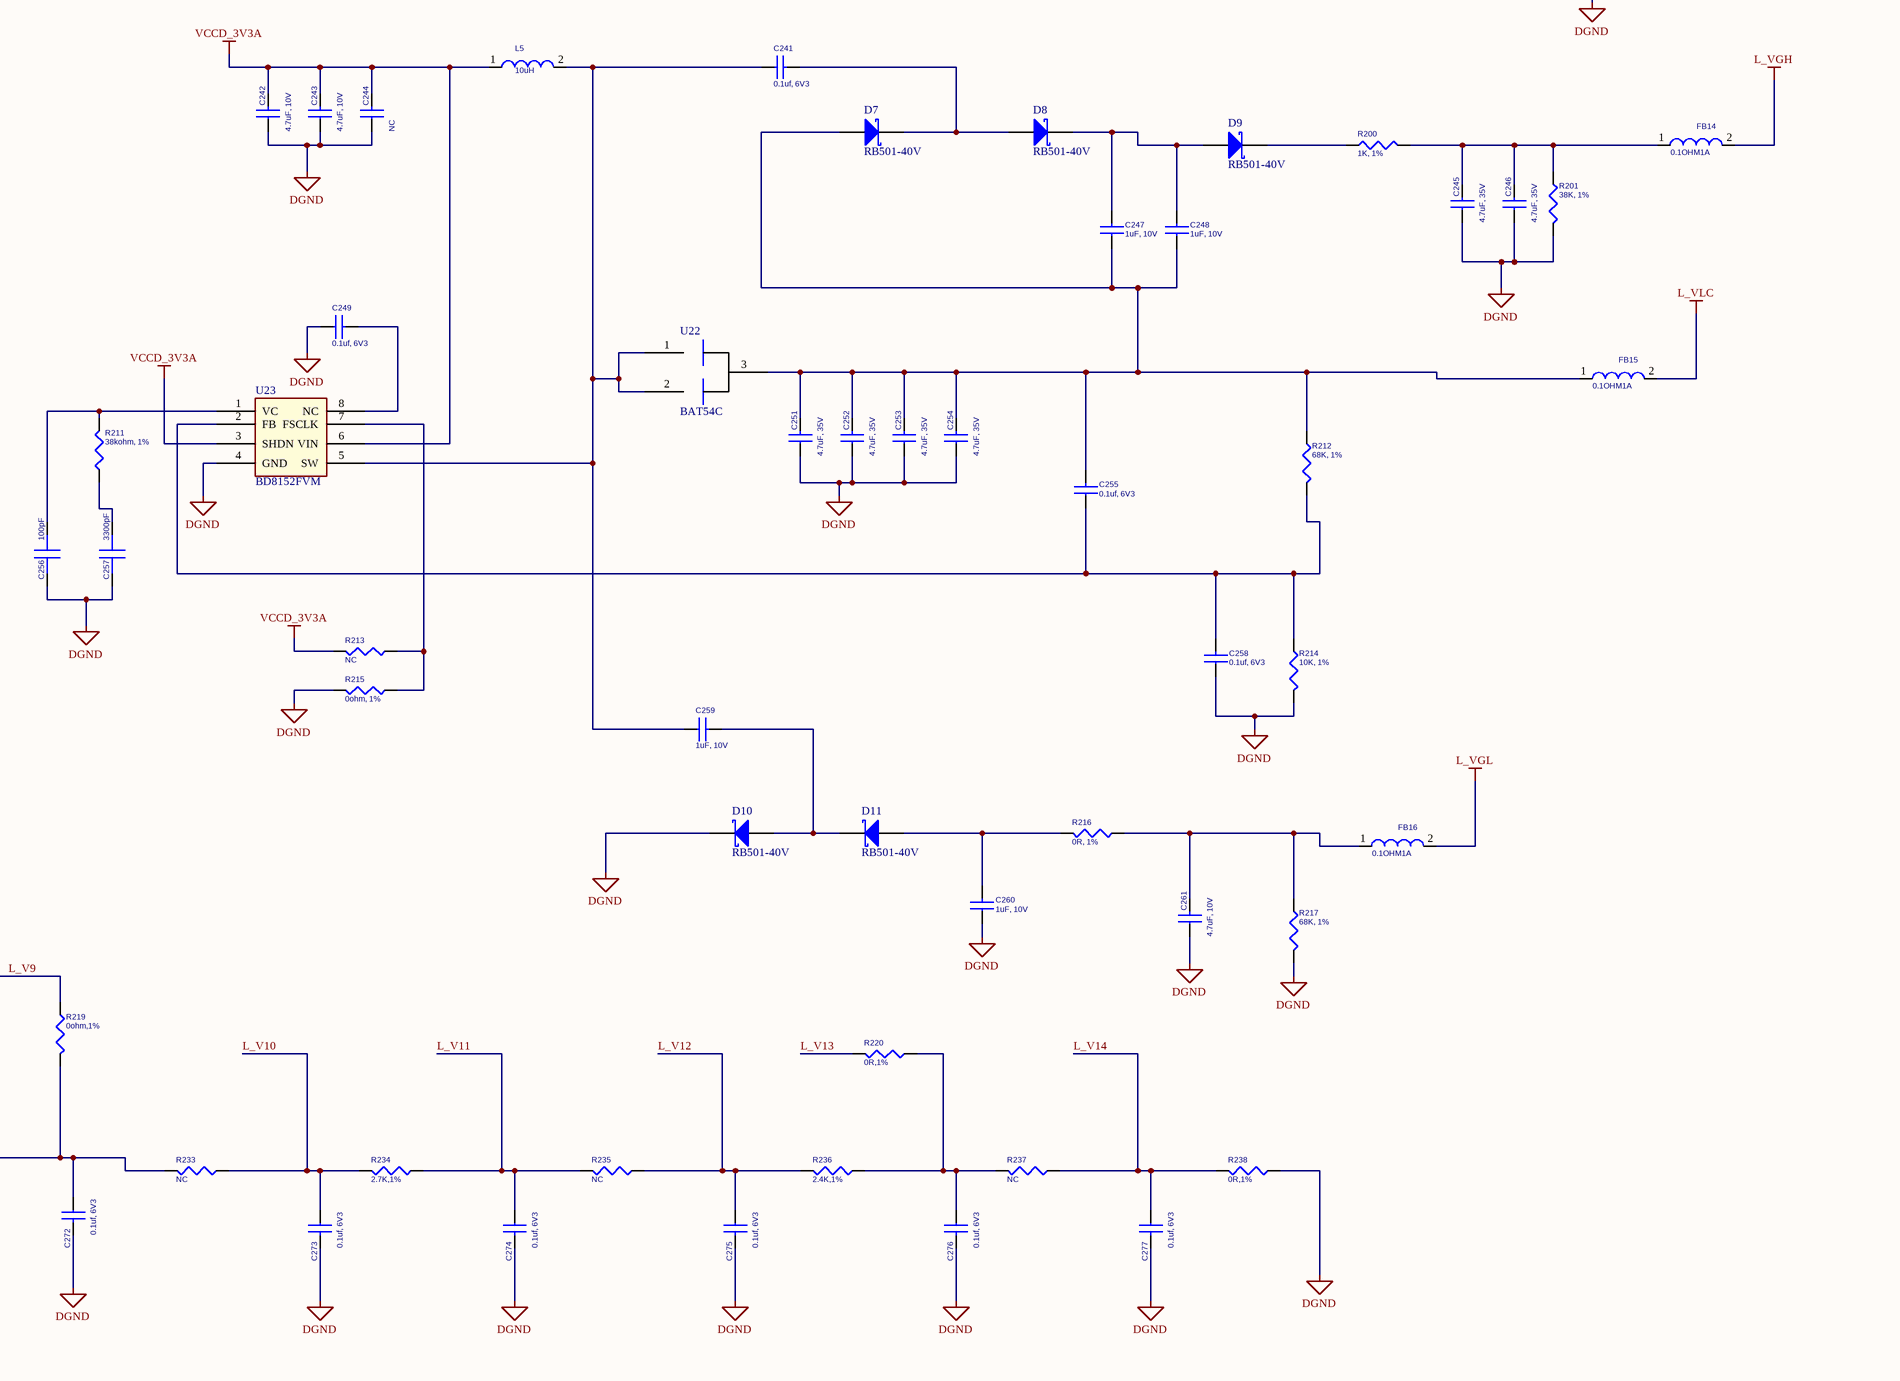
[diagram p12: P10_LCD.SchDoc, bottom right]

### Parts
C147  value 68uF/20v  [7343T]  (hidden comment: EEE-FK1A220R)
C149  value 220uF/16v  [7343T]  (hidden comment: 16SVP180M)
C156  47pF, 6.3V  [402]
C157  47pF, 6.3V  [402]
C160  47pF, 6.3V  [402]
C161  47pF, 6.3V  [402]
C162  47pF, 6.3V  [402]
C163  47pF, 6.3V  [402]
C164  47pF, 6.3V  [402]
C165  47pF, 6.3V  [402]
C166  47pF, 6.3V  [402]
C167  47pF, 6.3V  [402]
C168  47pF, 6.3V  [402]
C169  47pF, 6.3V  [402]
C170  47pF, 6.3V  [402]
C171  47pF, 6.3V  [402]
C172  47pF, 6.3V  [402]
C173  47pF, 6.3V  [402]
C199  value 0.1UF  [0805]  (hidden comment: C1005X5R0J104K)
C200  2.2uF, 6V3  [0805]
C201  470pF, 50V  [402]
C202  0.1uf, 6V3  [402]
C203  value 0.1UF  [0805]  (hidden comment: GRM216R71H103KA01D)
C204  4.7uF, 10V  [805]
C205  4.7uF, 10V  [805]
C206  4.7uF, 10V  [805]
C207  0.1uf, 6V3  [402]
C208  0.1uf, 6V3  [402]
C209  0.1uf, 6V3  [402]
C210  0.1uf, 6V3  [402]
C211  0.1uf, 6V3  [402]
C212  0.1uf, 6V3  [402]
C213  0.1uf, 6V3  [402]
C214  0.1uf, 6V3  [402]
C215  0.1uf, 6V3  [402]
C216  0.1uf, 6V3  [402]
C217  0.1uf, 6V3  [402]
C218  0.1uf, 6V3  [402]
C219  0.1uf, 6V3  [402]
C220  33pF  [402]
C221  33pF  [402]
C222  33pF  [402]
C223  33pF  [402]
C224  33pF  [402]
C225  33pF  [402]
C226  33pF  [402]
C227  33pF  [402]
C228  33pF  [402]
C229  33pF  [402]
C230  0.1uf, 6V3  [402]
C231  0.1uf, 6V3  [402]
C232  0.1uf, 6V3  [402]
C233  33pF  [402]
C234  33pF  [402]
C235  33pF  [402]
C236  33pF  [402]
C237  33pF  [402]
C238  33pF  [402]
C239  33pF  [402]
C240  33pF  [402]
C241  0.1uf, 6V3  [402]
C242  4.7uF, 10V  [805]
C243  4.7uF, 10V  [805]
C244  NC  [805]
C245  4.7uF, 35V  [1210]
C246  4.7uF, 35V  [1210]
C247  1uF, 10V  [0805]
C248  1uF, 10V  [0805]
C249  0.1uf, 6V3  [402]
C250  1uF, 10V  [0805]
C251  4.7uF, 35V  [1210]
C252  4.7uF, 35V  [1210]
C253  4.7uF, 35V  [1210]
C254  4.7uF, 35V  [1210]
C255  0.1uf, 6V3  [402]
C256  100pF  [402]
C257  3300pF  [C0603]
C258  0.1uf, 6V3  [402]
C259  1uF, 10V  [0805]
C260  1uF, 10V  [0805]
C261  4.7uF, 10V  [805]
C262  Cap Pol1  value 4.7uF  [6032/case C]
C263  Cap Pol1  value 4.7uF  [6032/case C]
C264  0.1uf, 6V3  [402]
C265  0.1uf, 6V3  [402]
C266  0.1uf, 6V3  [402]
C267  0.1uf, 6V3  [402]
C268  0.1uf, 6V3  [402]
C269  0.1uf, 6V3  [402]
C270  0.1uf, 6V3  [402]
C271  0.1uf, 6V3  [402]
C272  0.1uf, 6V3  [402]
C273  0.1uf, 6V3  [402]
C274  0.1uf, 6V3  [402]
C275  0.1uf, 6V3  [402]
C276  0.1uf, 6V3  [402]
C277  0.1uf, 6V3  [402]
C281  value 5nF  [0805]  (hidden comment: CC0805KRX7R9BB561)
C282  value 0.01UF  [0805]  (hidden comment: GRM216R71H103KA01D)
D6  Diode  [DSO-C2/X3.3]
D7  RB501-40V  [DSO-C2/X2.3]
D8  RB501-40V  [DSO-C2/X2.3]
D9  RB501-40V  [DSO-C2/X2.3]
D10  RB501-40V  [DSO-C2/X2.3]
D11  RB501-40V  [DSO-C2/X2.3]
FB12  0.1OHM1A  [SM-7351-IND-0805]
FB13  0.1OHM1A  [SM-7351-IND-0805]
FB14  0.1OHM1A  [SM-7351-IND-0805]
FB15  0.1OHM1A  [SM-7351-IND-0805]
FB16  0.1OHM1A  [SM-7351-IND-0805]
FB17  0.1OHM1A,DNI  [SM-7351-IND-0805]
J2  JACK_BACKLIGHT  [JACK_BACKLIGHT]
L4  220uH  [L330]
L5  10uH  [2520]
M1  CSD17308Q3  [MOSFET_Q3]
P9  HDR_2X1  [HDR_2X1]
P18  FPC_CON_30X2  [FPC_CON_30X2]
R39  value 10k  [R0603]  (hidden comment: CRCW04021K00FKED)
R41  value 63.4k  [R0603]  (hidden comment: CRCW04027K68FKED)
R111  0ohm, 1%  [R0805]
R146  NC  [R0805]
R147  200K,1%  [R0805]
R148  100ohm,1%  [R0603]
R149  470K, 5%  [R0402]
R158  10k, 1%  [R0402]
R161  280K, 1%  [R0402]
R162  20K,1%  [R0805]
R166  NC  [R0603]
R168  value 100  [R0603]  (hidden comment: CRCW0402100RFKED)
R169  0ohm  [R0805]
R170  NC  [R0805]
R171  NC  [R0603]
R172  0R,1%  [R0805]
R173  value 226k  [R0603]  (hidden comment: CRCW040228K7FKED)
R174  100ohm,1%  [R0603]
R175  value 4.53K  [R0603]  (hidden comment: CRCW040211K0FKED)
R176  value 120m Ohm  [R2010]  (hidden comment: CSRN2010FK60L0)
R177  100ohm,1%  [R0603]
R178  10K,1%  [R0805]
R179  NC  [R0603]
R180  100ohm,1%  [R0603]
R181  100ohm,1%  [R0603]
R182  100ohm,1%  [R0603]
R183  NC  [R0805]
R184  100ohm,1%  [R0603]
R185  NC  [R0603]
R186  NC  [R0603]
R187  0ohm, 1%  [R0805]
R188  100ohm,1%  [R0603]
R189  0ohm, 1%  [R0805]
R190  NC  [R0805]
R191  NC  [R0805]
R192  100ohm,1%  [R0603]
R193  10kohm, 1%  [R0805]
R194  10kohm, 1%  [R0805]
R195  100ohm,1%  [R0603]
R196  100ohm,1%  [R0603]
R197  100ohm,1%  [R0603]
R198  0ohm,DNI  [R0805]
R199  0ohm,DNI  [R0805]
R200  1K, 1%  [R0805]
R201  38K, 1%  [R0805]
R202  10kohm, 1%,DNI  [R0805]
R203  1kohm, 1%  [R0805]
R204  NC  [R0805]
R205  NC  [R0805]
R206  1kohm, 1%  [R0805]
R207  0ohm,1%  [R0805]
R208  1Kohm,1%  [R0805]
R209  1Kohm,1%  [R0805]
R210  NC  [R0805]
R211  38kohm, 1%  [R0805]
R212  68K, 1%  [R0805]
R213  NC  [R0805]
R214  10K, 1%  [R0805]
R215  0ohm, 1%  [R0805]
R216  0R, 1%  [R0805]
R217  68K, 1%  [R0805]
R218  0ohm,1%  [R0805]
R219  0ohm,1%  [R0805]
R220  0R,1%  [R0805]
R221  0ohm,1%  [R0805]
R222  2.7K,1%  [R0805]
R223  0ohm,1%  [R0805]
R224  0ohm,1%  [R0805]
R225  NC  [R0805]
R226  2.4K,1%  [R0805]
R227  NC  [R0805]
R228  2.7K,1%  [R0805]
R229  NC  [R0805]
R230  10K,1%  [R0805]
R231  2.4K,1%  [R0805]
R232  10K,1%  [R0805]
R233  NC  [R0805]
R234  2.7K,1%  [R0805]
R235  NC  [R0805]
R236  2.4K,1%  [R0805]
R237  NC  [R0805]
R238  0R,1%  [R0805]
RA1  15R,RES_ARRAY  [R8_0603]
RA2  15R,RES_ARRAY  [R8_0603]
RA3  15R,RES_ARRAY  [R8_0603]
RA4  15R,RES_ARRAY  [R8_0603]
RA5  15R,RES_ARRAY  [R8_0603]
RA6  15R,RES_ARRAY  [R8_0603]
RA7  33R,RES_ARRAY  [R8_0603]
RA8  33R,RES_ARRAY  [R8_0603]
RA9  33R,RES_ARRAY  [R8_0603]
RA10  33R,RES_ARRAY  [R8_0603]
RA11  33R,RES_ARRAY  [R8_0603]
Radj1  Res Tap  value 5K  [RADJ]
U20  TL5209  [SO8-25X75/TL5209DR/8-SOIC]
U21  PVI2003A  [TQFP13-64 STD/PVI2003A]
U22  BAT54C  [SOT-23/BAT54C]
U23  BD8152FVM  [MSOP8/BD8152FVM]
U24  LM3478MA  [SOP8_LM3478]

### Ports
HDMI_INT, LCD_DATA0, LCD_DATA1, LCD_DATA2, LCD_DATA3, LCD_DATA4, LCD_DATA5, LCD_DATA6, LCD_DATA7, LCD_DATA8, LCD_DATA9, LCD_DATA10, LCD_DATA11, LCD_DATA12, LCD_DATA13, LCD_DATA14, LCD_DATA15, LCD_DE, LCD_HSYNC, LCD_PCLK, LCD_VSYNC

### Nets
DGND: C147.2(-) C149.2(-) C156.2 C157.2 C160.2 C161.2 C162.2 C163.2 C164.2 C165.2 C166.2 C167.2 C168.2 C169.2 C170.2 C171.2 C172.2 C173.2 C199.2 C200.2 C201.2 C202.2 C204.1 C205.1 C206.1 C207.2 C208.2 C209.2 C210.2 C211.2 C212.2 C213.2 C214.2 C215.2 C216.2 C217.2 C218.2 C219.2 C220.2 C221.2 C222.2 C223.2 C224.2 C225.2 C226.2 C227.2 C228.2 C229.2 C230.2 C231.2 C232.2 C233.2 C234.2 C235.2 C236.2 C237.2 C238.2 C239.2 C240.2 C242.1 C243.1 C244.1 C245.1 C246.1 C249.1 C250.2 C251.1 C252.1 C253.1 C254.1 C256.2 C257.2 C258.1 C260.1 C261.1 C262.2 C263.2 C264.2 C265.2 C266.2 C267.2 C268.2 C269.2 C270.2 C271.2 C272.2 C273.2 C274.2 C275.2 C276.2 C277.2 C281.2 C282.2 D10.2(K) J2.1(NEG) P18.2 P18.5 P18.13 P18.20 P18.31(FIX1) P18.32(FIX2) P18.33 P18.41 P18.49 P18.59 P18.61 P18.63(FIX1) P18.64(FIX2) R39.1 R149.2 R169.2(P2) R170.2(P2) R173.1 R175.2 R176.1 R178.2(P2) R190.2(P2) R191.2(P2) R198.2(P2) R199.2(P2) R201.1(P1) R207.2(P2) R208.2(P2) R209.2(P2) R210.2(P2) R214.1(P1) R215.1(P1) R217.1(P1) R238.2(P2) RA2.1 RA5.1 U20.5(GND) U20.6(GND) U20.7(GND) U20.8(GND) U21.25(VSS) U21.39(VSS) U21.49(VSS) U21.62(TEST) U23.4(GND) U24.4(AGND) U24.5(PGND)
L_VGH: C231.1 FB14.2 P18.58
L_VGL: C232.1 FB16.2 P18.62
L_VLC: FB15.2 P18.50 R162.1(P1) R223.1(P1)
SYS_5V: C200.1 U20.2(IN)
VCCD: C208.1 C209.1 C210.1 C211.1 C212.1 C213.1 C214.1 C215.1 C216.1 C217.1 C218.1 C219.1 C230.1 FB12.2 P18.3 P18.60 R146.1(P1) R147.1(P1) R183.1(P1) R193.1(P1) R194.1(P1) R202.1(P1) R203.1(P1) R204.1(P1) R205.1(P1) R206.1(P1) U21.17(VDD) U21.32(VDD) U21.64(VDD)
VCCD_3V3A: C205.2 C242.2 C243.2 C244.2 FB13.2 L5.1 R213.1(P1) U23.3(SHDN) U23.6(VIN)
VDD_3V3A: U20.1(EN)
VDD_3V3B: R158.1(P1)
VDD_3V3D: C202.1 C204.2 FB12.1 FB13.1 R161.1 U20.3(OUT)
VDD_5V0: FB17.1 P9.1
BI_H0: RA5.8 U21.48(BI0)
BI_H1: RA5.7 U21.47(BI1)
BI_H2: RA5.6 U21.46(BI2)
BI_H3: RA5.5 U21.45(BI3)
BI_H4: RA6.8 U21.44(BI4)
BI_H5: RA6.7 U21.43(BI5)
BO_H0: RA10.1 U21.24(BO0)
BO_H1: RA10.2 U21.23(BO1)
BO_H2: RA10.3 U21.22(BO2)
BO_H3: RA10.4 U21.21(BO3)
BO_H4: RA11.1 U21.20(BO4)
BO_H5: RA11.2 U21.19(BO5)
CLKH: R111.1(P1) U21.63(ICLK)
DENBH: R189.1(P1) R191.1(P1) U21.42(DENB)
GI_H0: RA3.6 U21.55(GI0)
GI_H1: RA3.5 U21.54(GI1)
GI_H2: RA4.8 U21.53(GI2)
GI_H3: RA4.7 U21.52(GI3)
GI_H4: RA4.6 U21.51(GI4)
GI_H5: RA4.5 U21.50(GI5)
GO_H0: RA8.3 U21.31(GO0)
GO_H1: RA8.4 U21.30(GO1)
GO_H2: RA9.1 U21.29(GO2)
GO_H3: RA9.2 U21.28(GO3)
GO_H4: RA9.3 U21.27(GO4)
GO_H5: RA9.4 U21.26(GO5)
HDMI_INT: R158.2(P2) ; port HDMI_INT
HSYNCH: RA1.6 U21.40(HSYNC)
L_BO0: C235.1 P18.21 RA10.8
L_BO1: C236.1 P18.22 RA10.7
L_BO2: C237.1 P18.23 RA10.6
L_BO3: C238.1 P18.24 RA10.5
L_BO4: C239.1 P18.25 RA11.8
L_BO5: C240.1 P18.26 RA11.7
L_CKHH: P18.4 R183.2(P2) R187.1(P1) R190.1(P1)
L_CKV: R182.1(P1) U21.5(CKV)
L_CKVH: P18.55 R182.2(P2)
L_CLK1: R187.2(P2) U21.18(OCLK)
L_DIO1: P18.1 R148.2(P2) R171.2(P2)
L_DIO2: P18.30 R166.2(P2) R174.2(P2)
L_GO0: C226.1 P18.14 RA8.6
L_GO1: C227.1 P18.15 RA8.5
L_GO2: C228.1 P18.16 RA9.8
L_GO3: C229.1 P18.17 RA9.7
L_GO4: C233.1 P18.18 RA9.6
L_GO5: C234.1 P18.19 RA9.5
L_LDH: P18.27 R177.2(P2)
L_OE: R180.1(P1) U21.4(OEV)
L_OEH: P18.53 R180.2(P2)
L_POL: R188.1(P1) U21.10(POL)
L_POLH: P18.29 R185.2(P2) R188.2(P2)
L_REV: P18.28 R146.2(P2) R169.1(P1)
L_RLB: P18.6 R197.2(P2)
L_RO0: C220.1 P18.7 RA7.8
L_RO1: C221.1 P18.8 RA7.7
L_RO2: C222.1 P18.9 RA7.6
L_RO3: C223.1 P18.10 RA7.5
L_RO4: C224.1 P18.11 RA8.8
L_RO5: C225.1 P18.12 RA8.7
L_SEL0: R204.2(P2) R208.1(P1) U21.16(SEL0)
L_SEL1: R205.2(P2) R209.1(P1) U21.15(SEL1)
L_SEL2: R206.2(P2) R210.1(P1) U21.14(SEL2)
L_SPOL: R185.1(P1) U21.9(SPOL)
L_STB: R177.1(P1) U21.11(STB)
L_STH1: R148.1(P1) R166.1(P1) U21.12(STH1)
L_STH2: R171.1(P1) R174.1(P1) U21.13(STH2)
L_STV1: R179.1(P1) R181.1(P1) U21.8(STV1)
L_STV2: R184.1(P1) R186.1(P1) U21.3(STV2)
L_STVDH: P18.57 R181.2(P2) R186.2(P2)
L_STVUH: P18.56 R179.2(P2) R184.2(P2)
L_UDB: P18.54 R196.2(P2)
L_V1: C264.1 P18.34 R224.2(P2) R225.1(P1)
L_V2: P18.35 R218.2(P2)
L_V3: C266.1 P18.36 R226.2(P2) R227.1(P1)
L_V4: C267.1 P18.37 R227.2(P2) R228.1(P1)
L_V5: C268.1 P18.38 R228.2(P2) R229.1(P1)
L_V6: P18.39 R221.2(P2)
L_V7: C270.1 P18.40 R222.1(P1) R230.2(P2) R231.1(P1)
L_V8: C271.1 P18.42 R222.2(P2) R231.2(P2) R232.1(P1)
L_V9: P18.43 R219.2(P2)
L_V10: C273.1 P18.44 R233.2(P2) R234.1(P1)
L_V11: C274.1 P18.45 R234.2(P2) R235.1(P1)
L_V12: C275.1 P18.46 R235.2(P2) R236.1(P1)
L_V13: P18.47 R220.1(P1)
L_V14: C277.1 P18.48 R237.2(P2) R238.1(P1)
L_VCOM: C206.2 C207.1 P18.51 R172.2(P2) R178.1(P1) Radj1.2(B)
L_XON: P18.52 R147.2(P2) R170.1(P1)
LCD_DATA0: C173.1 RA5.2 ; port LCD_DATA0
LCD_DATA1: C171.1 RA5.3 ; port LCD_DATA1
LCD_DATA2: C172.1 RA5.4 ; port LCD_DATA2
LCD_DATA3: C170.1 RA6.1 ; port LCD_DATA3
LCD_DATA4: C169.1 RA6.2 ; port LCD_DATA4
LCD_DATA5: C163.1 RA3.3 ; port LCD_DATA5
LCD_DATA6: C162.1 RA3.4 ; port LCD_DATA6
LCD_DATA7: C161.1 RA4.1 ; port LCD_DATA7
LCD_DATA8: C160.1 RA4.2 ; port LCD_DATA8
LCD_DATA9: C157.1 RA4.3 ; port LCD_DATA9
LCD_DATA10: C156.1 RA4.4 ; port LCD_DATA10
LCD_DATA11: C168.1 RA2.2 ; port LCD_DATA11
LCD_DATA12: C167.1 RA2.3 ; port LCD_DATA12
LCD_DATA13: C166.1 RA2.4 ; port LCD_DATA13
LCD_DATA14: C165.1 RA3.1 ; port LCD_DATA14
LCD_DATA15: C164.1 RA3.2 ; port LCD_DATA15
LCD_DE: RA6.3 ; port LCD_DE
LCD_HSYNC: RA1.3 ; port LCD_HSYNC
LCD_PCLK: R111.2(P2) ; port LCD_PCLK
LCD_VSYNC: RA1.2 ; port LCD_VSYNC
RESET: C250.1 R203.2(P2) U21.1(RESET)
RI_H0: RA2.8 U21.61(RI0)
RI_H1: RA2.7 U21.60(RI1)
RI_H2: RA2.6 U21.59(RI2)
RI_H3: RA2.5 U21.58(RI3)
RI_H4: RA3.8 U21.57(RI4)
RI_H5: RA3.7 U21.56(RI5)
RLH: R195.2(P2) U21.7(RL)
RO_H0: RA7.1 U21.38(RO0)
RO_H1: RA7.2 U21.37(RO1)
RO_H2: RA7.3 U21.36(RO2)
RO_H3: RA7.4 U21.35(RO3)
RO_H4: RA8.1 U21.34(RO4)
RO_H5: RA8.2 U21.33(RO5)
SEL_I_DATA: R202.2(P2) R207.1(P1) U21.2(SEL_I_DATA)
UDH: R192.2(P2) U21.6(UD)
VSYNCH: RA1.7 U21.41(VSYNC)
NetC147_1: C147.1(+) C199.1 FB17.2 L4.1 P9.2 U24.8(VIN)
NetC149_1: C149.1(+) D6.2(K) J2.2(PLUS) R41.1
NetC201_1: C201.1 R149.1 R161.2 U20.4(ADJ)
NetC203_1: C203.1 C281.1 U24.2(COMP)
NetC203_2: C203.2 R175.1
NetC241_1: C241.1 C259.1 L5.2 U22.1 U22.2 U23.5(SW)
NetC241_2: C241.2 D7.2(K) D8.1(A)
NetC245_2: C245.2 C246.2 FB14.1 R200.1(P1) R201.2(P2)
NetC247_1: C247.1 C248.1 C251.2 C252.2 C253.2 C254.2 C255.2 D7.1(A) FB15.1 R212.2(P2) U22.3
NetC247_2: C247.2 C248.2 D8.2(K) D9.1(A)
NetC249_2: C249.2 U23.8(NC)
NetC255_1: C255.1 C258.2 R212.1(P1) R214.2(P2) U23.2(FB)
NetC256_1: C256.1 R211.1(P1) U23.1(VC)
NetC257_1: C257.1 R211.2(P2)
NetC259_2: C259.2 D10.1(A) D11.2(K)
NetC260_2: C260.2 D11.1(A) R216.1(P1)
NetC261_2: C261.2 FB16.1 R216.2(P2) R217.2(P2)
NetC262_1: C262.1 C263.1 R223.2(P2) R224.1(P1)
NetC265_1: C265.1 R218.1(P1) R225.2(P2) R226.1(P1)
NetC269_1: C269.1 R221.1(P1) R229.2(P2) R230.1(P1)
NetC272_1: C272.1 R219.1(P1) R232.2(P2) R233.1(P1)
NetC276_1: C276.1 R220.2(P2) R236.2(P2) R237.1(P1)
NetC282_1: C282.1 R168.2 U24.1(ISEN)
NetD6_1: D6.1(A) L4.2 M1.8(D)
NetD9_2: D9.2(K) R200.2(P2)
NetM1_2: M1.2(S) R168.1 R176.2
NetM1_4: M1.4(G) U24.6(DR)
NetR39_2: R39.2 R41.2 U24.3(FB)
NetR162_2: R162.2(P2) R172.1(P1) Radj1.3(TAP)
NetR173_2: R173.2 U24.7(FA/SD)
NetR189_2: R189.2(P2) RA6.6
NetR192_1: R192.1(P1) R194.2(P2) R196.1(P1) R199.1(P1)
NetR193_2: R193.2(P2) R195.1(P1) R197.1(P1) R198.1(P1)
NetR213_2: R213.2(P2) R215.2(P2) U23.7(FSCLK)

Not connected (* = marked no-connect by the designer): RA1 1 4 5 8; RA6 4 5; RA11 3 4 5 6; Radj1 1(A)

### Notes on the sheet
- RED
- GREEN
- BLUE
- LCD同组信号线需要用走等长蛇形线！

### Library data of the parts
C147 = EEE-FK1A220R: Manufacturer Name: Panasonic
C149 = 16SVP180M: Manufacturer Name: Sanyo
C156 C157 C160-C173 C256 C257 = CAP SMD: CAP CER 47PF 50V 5% NP0 0402; Manufacturer: TDK Corporation; Manufacturer Part Number: C1005C0G1H470J050BA; Tolerance: ?%; Temperature Coefficient: C0G, NP0
C199 = C1005X5R0J104K: Manufacturer Name: TDK
C200 = CAP_2.2uF_X5R_6.3V_10%_0402: CAP CER 2.2UF 6.3V 10% X5R 0402; Manufacturer: TDK Corporation; Manufacturer Part Number: C1005X5R0J225K050BC; Capacitance: 2.2µF; Tolerance: ?0%
C201 C220-C229 C233-C240 = CAP_2.2uF_X5R_6.3V_10%_0402: CAP CER 470PF 50V 10% X7R 0402; Manufacturer: Murata Electronics North America; Manufacturer Part Number: GRM155R71H471KA01D; Tolerance: ?0%
C202 C207-C219 C230-C232 C241 C249 C255 C258 C264-C277 = CAP_0.1uF_X7R_16V_10% 0402: as C131 on sheet P09_Ethernet
C203 C282 = GRM216R71H103KA01D: GRM216R71H103KA0; Manufacturer Name: MuRata
C204-C206 C242-C246 C251-C254 C261 = CAP_10uF_Y5V_10V_10%_0805: CAP CER 10UF 10V Y5V 0805; Manufacturer: TDK Corporation; Manufacturer Part Number: C2012Y5V1A106Z; Capacitance: 10µF; Tolerance: -20%, +80%; Temperature Coefficient: Y5V (F)
C247 C248 C250 C259 C260 = CAP_1.0UF_X5R_10V_10%_0402: as C134 on sheet P09_Ethernet
C262 C263 = Cap Pol1: Polarized Capacitor (Radial)
C281 = CC0805KRX7R9BB561: CC0805KRX7R9BB56; Manufacturer Name: Yageo America
D6 = Diode: Default Diode
D7-D11 = D Schottky: Schottky Diode
FB12-FB17 = FER_180_200_0: FERRITE 800MA 150 OHM 0805 SMD; PartName: FerriteBead150ohm800mA; Mfr: Steward; MfrNum: LI0805H151R-10; TIIntPartnumber: 1L0010; Manufacturer: Laird-Signal Integrity Products; Vendor: Digikey; Impedance @ Frequency: 150 Ohm @ 100MHz; DC Resistance (DCR): 150 mOhm Max; Filter Type: Differential Mode - Single
L4 L5 = IND_2.2uH_2.6A_10%_SMD: INDUCTOR 2.2UH 20% 1300MA 1008; PartName: 2.2uH10%2.6Asmd; Mfr: TDK; MfrNum: VLCF5020T-2R2N2R6-3; TIIntPartnumber: 1L0025; Manufacturer: Murata Electronics North America; Manufacturer Part Number: LQM2HPN2R2MG0L; Vendor: Digikey; Cost100: 1.11; Cost10K: 0.37; Inductance: 2.2µH; Current Rating: 1.3A; Tolerance: ?0%; Shielding: Shielded; DC Resistance (DCR): 100 mOhm Max; Frequency - Self Resonant: 40MHz; Frequency - Test: 1MHz
M1 = M2_X
R39 = CRCW04021K00FKED: Manufacturer Name: Vishay-Dale
R41 = CRCW04027K68FKED: Manufacturer Name: Vishay-Dale
R111 R146-R148 R158 R162 R166 R169-R172 R174 R177-R238 = RES SMD: as R2 on sheet P08_NandFlash
R149 = RES_470_1/10W_5%_0402: RES 470K OHM 1/16W 1% 0402 SMD; Manufacturer: Yageo; Manufacturer Part Number: RC0402FR-07470KL; Power (Watts): 0.063W, 1/16W; Temperature Coefficient: ?00ppm/°C; Tolerance: ?%
R161 = RES_470_1/10W_5%_0402: RES 280K OHM 1/16W 1% 0402 SMD; Manufacturer: Stackpole Electronics Inc; Manufacturer Part Number: RMCF0402FT280K; Power (Watts): 0.063W, 1/16W; Temperature Coefficient: ?00ppm/°C; Tolerance: ?%
R168 = CRCW0402100RFKED: Manufacturer Name: Vishay-Dale
R173 = CRCW040228K7FKED: Manufacturer Name: Vishay-Dale
R175 = CRCW040211K0FKED: Manufacturer Name: Vishay-Dale
R176 = CSRN2010FK60L0: Manufacturer Name: Stackpole Electronics Inc
RA1-RA11 = RES_ARRAY
Radj1 = Res Tap: Tapped Resistor; Sim Note: Enter the Resistance value and the set point into parameter fields.; Set Position: 0.5
U20 = TL5209: IC LDO VOLT REG 500MA 8-SOIC; Manufacturer: Texas Instruments; Manufacturer Part Number: TL5209DR; Regulator Topology: Positive Adjustable; Voltage - Output: 2.5 V ~ 6.5 V; Voltage - Input: 2.5 V ~ 16 V; Voltage - Dropout (Typical): 0.35V @ 500mA; Number of Regulators: 1; Current - Output: 500mA (Max)
U24 = LM3478MM/NOPB: Manufacturer Name: Texas Instruments; Value: UNLISTED

## Sheet P11_SDcard.SchDoc
size A3
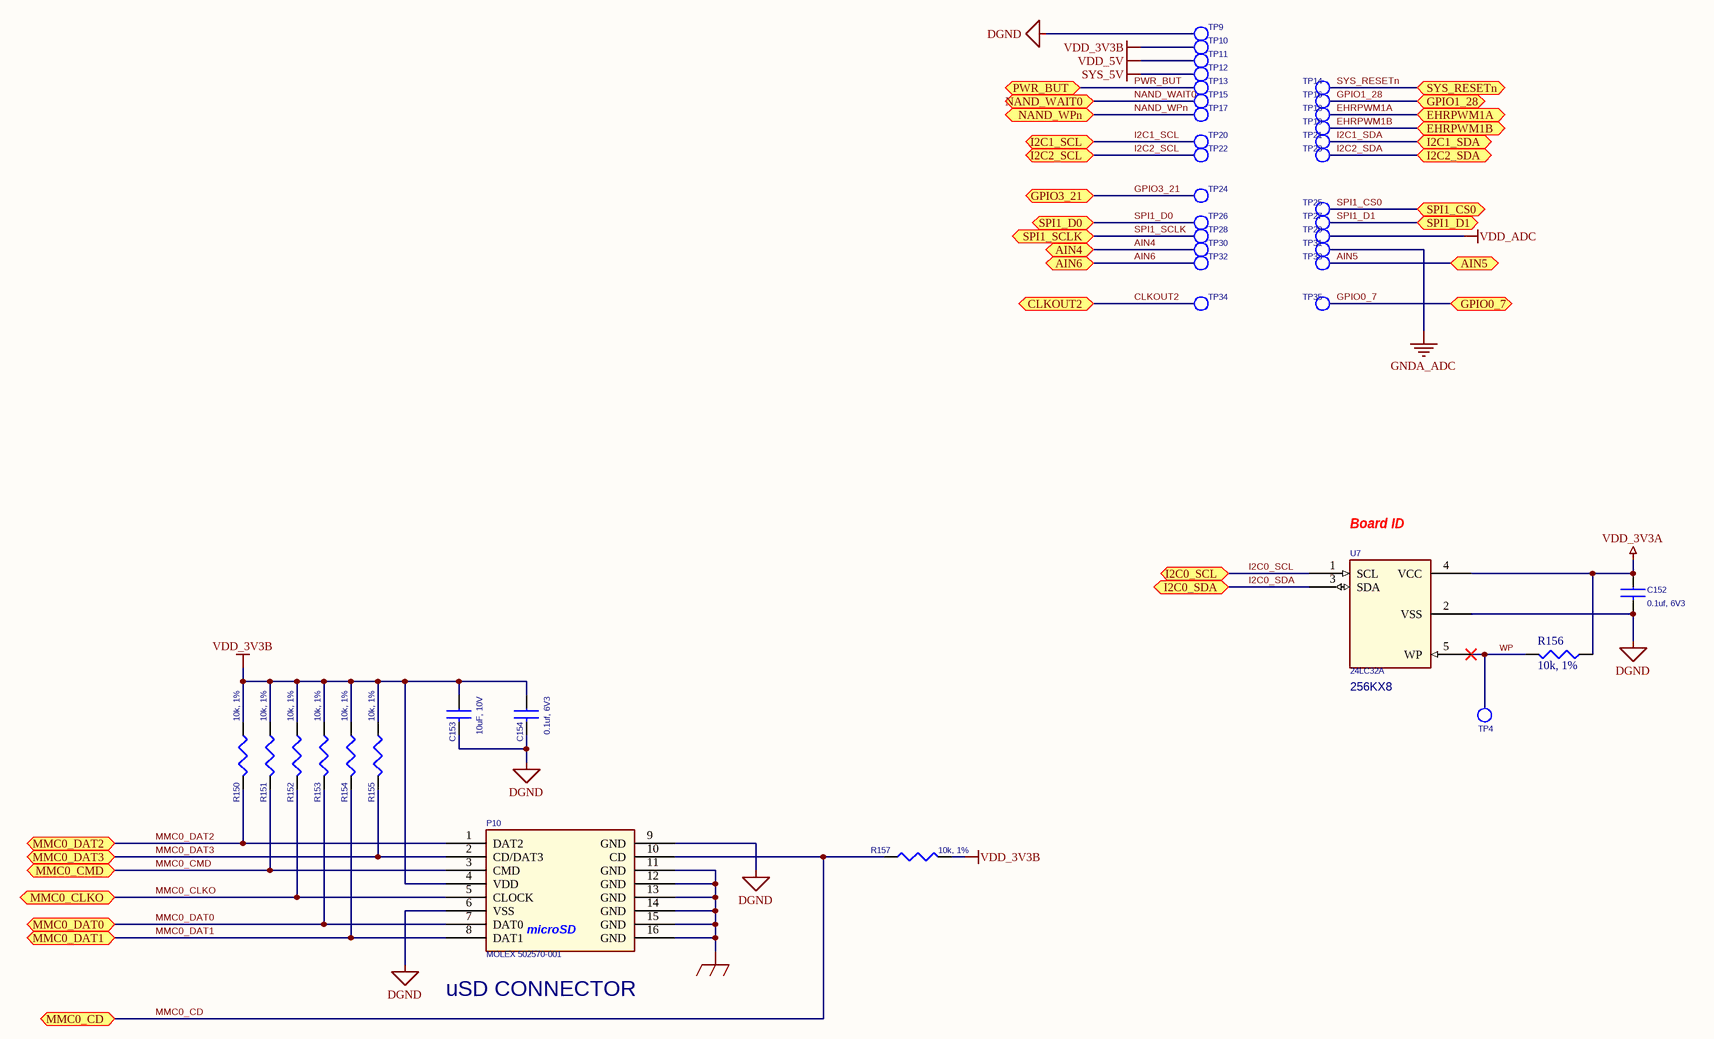
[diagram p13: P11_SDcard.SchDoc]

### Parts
C152  0.1uf, 6V3  [402]
C153  10uF, 10V  [805]
C154  0.1uf, 6V3  [402]
P10  MOLEX 502570-001  [SD-MICRO-SCHA5B0300]
R150  10k, 1%  [R0402]
R151  10k, 1%  [R0402]
R152  10k, 1%  [R0402]
R153  10k, 1%  [R0402]
R154  10k, 1%  [R0402]
R155  10k, 1%  [R0402]
R156  10k, 1%  [R0402]
R157  10k, 1%  [R0402]
TP4  TESTPT1  [tp1-8040]  (value not drawn)  (no BOM)
TP9  TESTPT1  [tp1-8040]  (value not drawn)  (no BOM)
TP10  TESTPT1  [tp1-8040]  (value not drawn)  (no BOM)
TP11  TESTPT1  [tp1-8040]  (value not drawn)  (no BOM)
TP12  TESTPT1  [tp1-8040]  (value not drawn)  (no BOM)
TP13  TESTPT1  [tp1-8040]  (value not drawn)  (no BOM)
TP14  TESTPT1  [tp1-8040]  (value not drawn)  (no BOM)
TP15  TESTPT1  [tp1-8040]  (value not drawn)  (no BOM)
TP16  TESTPT1  [tp1-8040]  (value not drawn)  (no BOM)
TP17  TESTPT1  [tp1-8040]  (value not drawn)  (no BOM)
TP18  TESTPT1  [tp1-8040]  (value not drawn)  (no BOM)
TP19  TESTPT1  [tp1-8040]  (value not drawn)  (no BOM)
TP20  TESTPT1  [tp1-8040]  (value not drawn)  (no BOM)
TP21  TESTPT1  [tp1-8040]  (value not drawn)  (no BOM)
TP22  TESTPT1  [tp1-8040]  (value not drawn)  (no BOM)
TP23  TESTPT1  [tp1-8040]  (value not drawn)  (no BOM)
TP24  TESTPT1  [tp1-8040]  (value not drawn)  (no BOM)
TP25  TESTPT1  [tp1-8040]  (value not drawn)  (no BOM)
TP26  TESTPT1  [tp1-8040]  (value not drawn)  (no BOM)
TP27  TESTPT1  [tp1-8040]  (value not drawn)  (no BOM)
TP28  TESTPT1  [tp1-8040]  (value not drawn)  (no BOM)
TP29  TESTPT1  [tp1-8040]  (value not drawn)  (no BOM)
TP30  TESTPT1  [tp1-8040]  (value not drawn)  (no BOM)
TP31  TESTPT1  [tp1-8040]  (value not drawn)  (no BOM)
TP32  TESTPT1  [tp1-8040]  (value not drawn)  (no BOM)
TP33  TESTPT1  [tp1-8040]  (value not drawn)  (no BOM)
TP34  TESTPT1  [tp1-8040]  (value not drawn)  (no BOM)
TP35  TESTPT1  [tp1-8040]  (value not drawn)  (no BOM)
U7  24LC32A  [SOT23-5/24LC32AT-I /SOT-23-5]

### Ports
AIN4, AIN5, AIN6, CLKOUT2, EHRPWM1A, EHRPWM1B, GPIO0_7, GPIO1_28, GPIO3_21, I2C0_SCL, I2C0_SDA, I2C1_SCL, I2C1_SDA, I2C2_SCL, I2C2_SDA, MMC0_CD, MMC0_CLKO, MMC0_CMD, MMC0_DAT0, MMC0_DAT1, MMC0_DAT2, MMC0_DAT3, NAND_WAIT0, NAND_WPn, PWR_BUT, SPI1_CS0, SPI1_D0, SPI1_D1, SPI1_SCLK, SYS_RESETn

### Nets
DGND: C152.2 C153.2 C154.2 P10.6(VSS) P10.9(GND) TP9.1(TP) U7.2(VSS)
GND_EARTH: P10.11(GND) P10.12(GND) P10.13(GND) P10.14(GND) P10.15(GND) P10.16(GND)
GNDA_ADC: TP31.1(TP)
SYS_5V: TP12.1(TP)
VDD_3V3A: C152.1 R156.1 U7.4(VCC)
VDD_3V3B: C153.1 C154.1 P10.4(VDD) R150.1 R151.1 R152.1 R153.1 R154.1 R155.1 R157.2 TP10.1(TP)
VDD_5V: TP11.1(TP)
VDD_ADC: TP29.1(TP)
AIN4: TP30.1(TP) ; port AIN4
AIN5: TP33.1(TP) ; port AIN5
AIN6: TP32.1(TP) ; port AIN6
CLKOUT2: TP34.1(TP) ; port CLKOUT2
EHRPWM1A: TP18.1(TP) ; port EHRPWM1A
EHRPWM1B: TP19.1(TP) ; port EHRPWM1B
GPIO0_7: TP35.1(TP) ; port GPIO0_7
GPIO1_28: TP16.1(TP) ; port GPIO1_28
GPIO3_21: TP24.1(TP) ; port GPIO3_21
I2C0_SCL: U7.1(SCL) ; port I2C0_SCL
I2C0_SDA: U7.3(SDA) ; port I2C0_SDA
I2C1_SCL: TP20.1(TP) ; port I2C1_SCL
I2C1_SDA: TP21.1(TP) ; port I2C1_SDA
I2C2_SCL: TP22.1(TP) ; port I2C2_SCL
I2C2_SDA: TP23.1(TP) ; port I2C2_SDA
MMC0_CD: P10.10(CD) R157.1 ; port MMC0_CD
MMC0_CLKO: P10.5(CLOCK) R152.2 ; port MMC0_CLKO
MMC0_CMD: P10.3(CMD) R151.2 ; port MMC0_CMD
MMC0_DAT0: P10.7(DAT0) R153.2 ; port MMC0_DAT0
MMC0_DAT1: P10.8(DAT1) R154.2 ; port MMC0_DAT1
MMC0_DAT2: P10.1(DAT2) R150.2 ; port MMC0_DAT2
MMC0_DAT3: P10.2(CD/DAT3) R155.2 ; port MMC0_DAT3
NAND_WAIT0: TP15.1(TP) ; port NAND_WAIT0
NAND_WPn: TP17.1(TP) ; port NAND_WPn
PWR_BUT: TP13.1(TP) ; port PWR_BUT
SPI1_CS0: TP25.1(TP) ; port SPI1_CS0
SPI1_D0: TP26.1(TP) ; port SPI1_D0
SPI1_D1: TP27.1(TP) ; port SPI1_D1
SPI1_SCLK: TP28.1(TP) ; port SPI1_SCLK
SYS_RESETn: TP14.1(TP) ; port SYS_RESETn
WP: R156.2 TP4.1(TP) U7.5(WP)

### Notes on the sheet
- (near U7) Board ID
- (near U7) 256KX8
- (near P10) uSD CONNECTOR

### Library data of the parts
C152 C154 = CAP_0.1uF_X7R_16V_10% 0402: as C131 on sheet P09_Ethernet
C153 = CAP_10uF_Y5V_10V_10%_0805: CAP CER 10UF 10V Y5V 0805; Manufacturer: TDK Corporation; Manufacturer Part Number: C2012Y5V1A106Z; Capacitance: 10µF; Temperature Coefficient: Y5V (F); Tolerance: -20%, +80%
P10 = microSD_CONN_2: CONN MICRO SD R/A PUSH-PUSH SMD; Manufacturer: Molex Inc; Manufacturer Part Number: 5025700893; Card Type: Secure Digital - microSD?TransFlash; Number of Positions: 10 (8 + 2); Connector Type: Connector and Ejector; Insertion, Removal Method: Push In, Push Out
R150-R157 = RES_10K_1/16W_1%_0402: as R96 on sheet P07_DDR3_SDRAM
U7 = 24LC32A: IC EEPROM 32KBIT 400KHZ SOT23-5; Manufacturer: Microchip Technology; Manufacturer Part Number: 24LC32AT-I/OT; Format - Memory: EEPROMs - Serial; Memory Size: 32K (4K x 8); Interface: I²C, 2-Wire Serial; Voltage - Supply: 2.5 V ~ 5.5 V

## Sheet P12_Exp_Audio.SchDoc
size A2
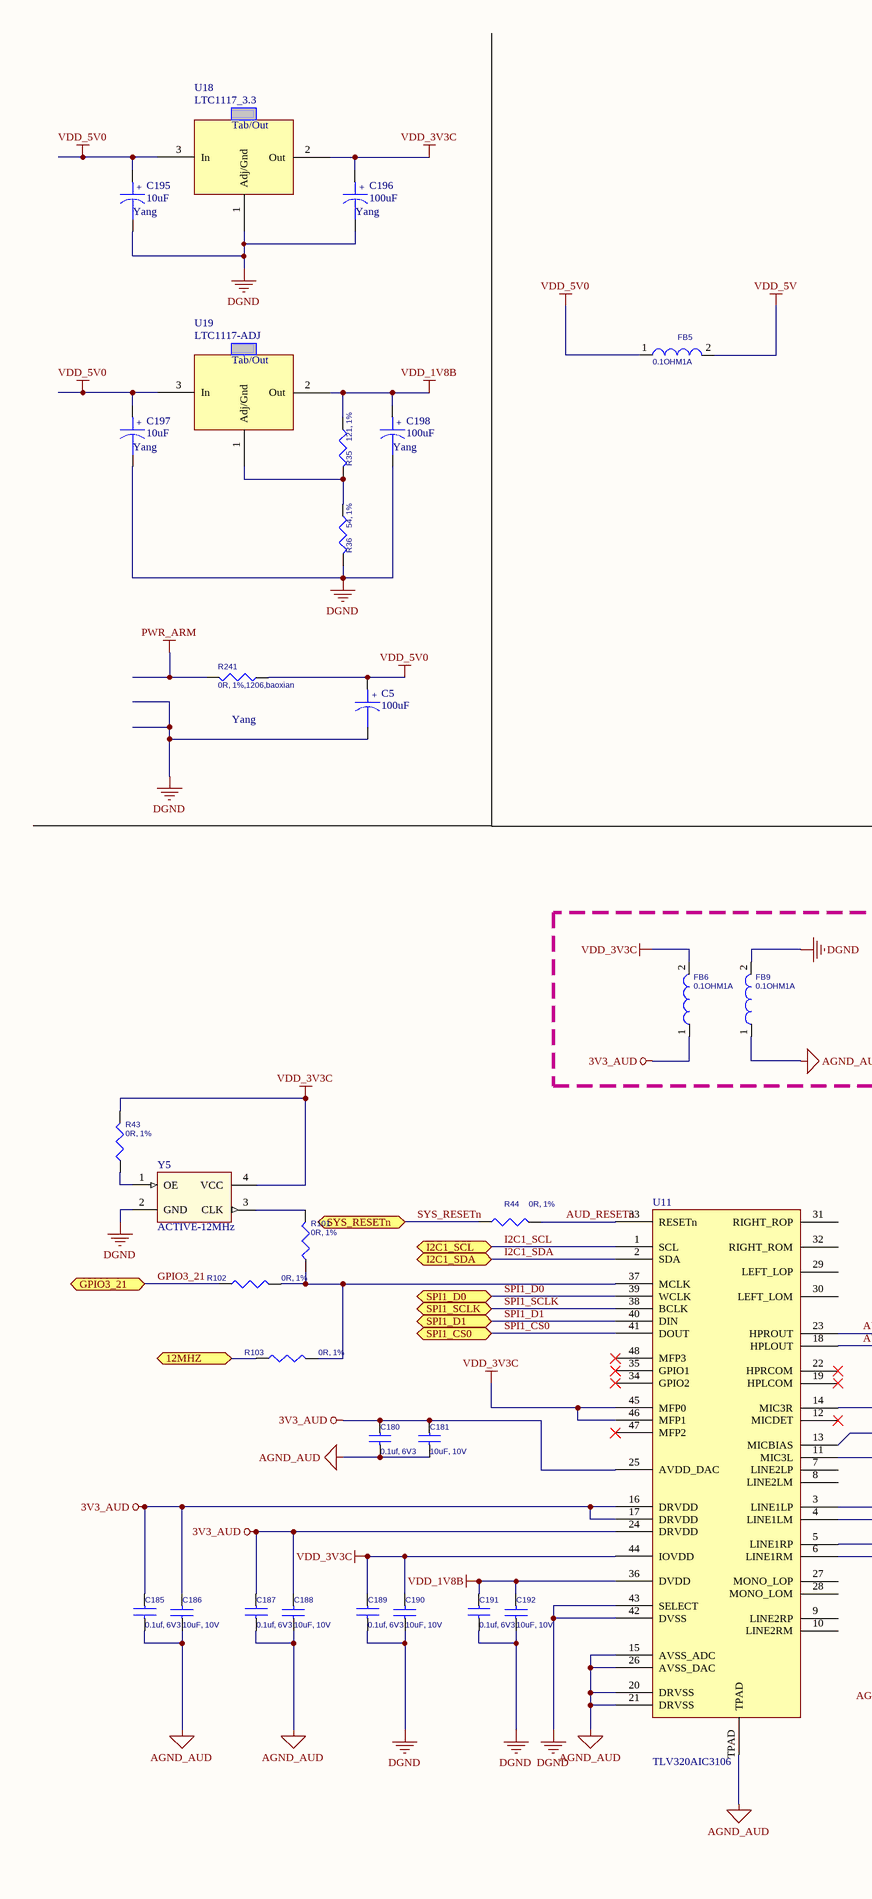
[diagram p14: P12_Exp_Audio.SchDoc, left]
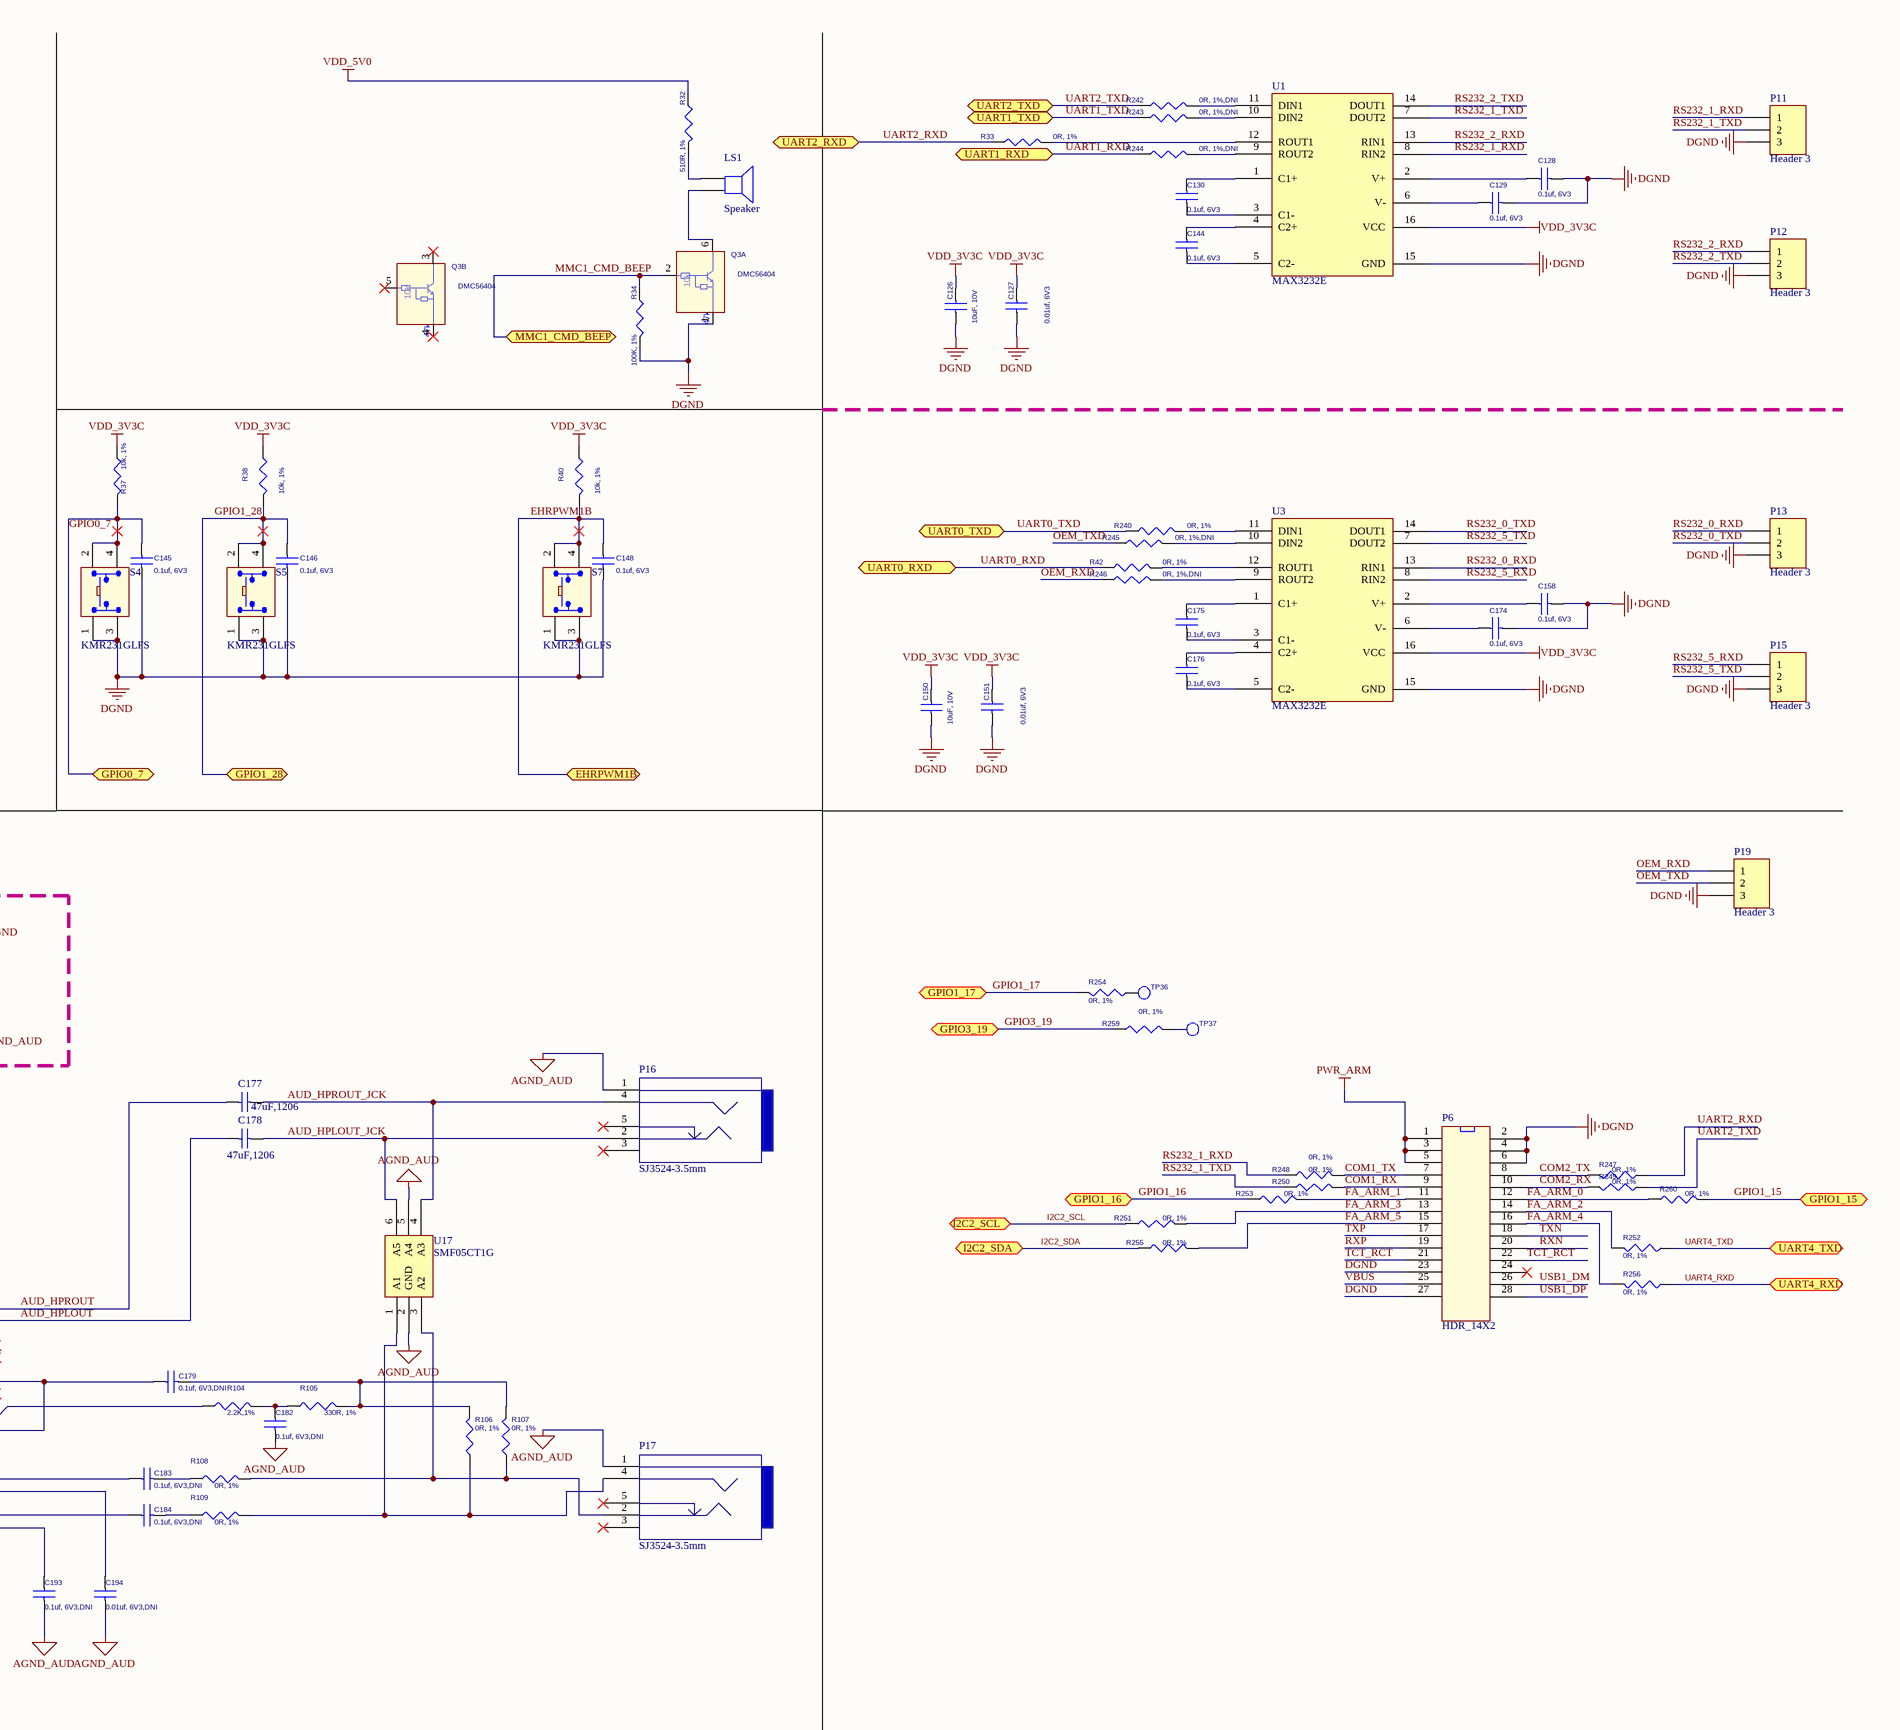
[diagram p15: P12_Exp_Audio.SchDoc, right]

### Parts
C5  100uF  [7343T]
C126  10uF, 10V  [805]
C127  0.01uf, 6V3  [402]
C128  0.1uf, 6V3  [402]
C129  0.1uf, 6V3  [402]
C130  0.1uf, 6V3  [402]
C144  0.1uf, 6V3  [402]
C145  0.1uf, 6V3  [402]
C146  0.1uf, 6V3  [402]
C148  0.1uf, 6V3  [402]
C150  10uF, 10V  [805]
C151  0.01uf, 6V3  [402]
C158  0.1uf, 6V3  [402]
C174  0.1uf, 6V3  [402]
C175  0.1uf, 6V3  [402]
C176  0.1uf, 6V3  [402]
C177  47uF,1206  [1206]
C178  47uF,1206  [1206]
C179  0.1uf, 6V3,DNI  [402]
C180  0.1uf, 6V3  [402]
C181  10uF, 10V  [805]
C182  0.1uf, 6V3,DNI  [402]
C183  0.1uf, 6V3,DNI  [402]
C184  0.1uf, 6V3,DNI  [402]
C185  0.1uf, 6V3  [402]
C186  10uF, 10V  [805]
C187  0.1uf, 6V3  [402]
C188  10uF, 10V  [805]
C189  0.1uf, 6V3  [402]
C190  10uF, 10V  [805]
C191  0.1uf, 6V3  [402]
C192  10uF, 10V  [805]
C193  0.1uf, 6V3,DNI  [402]
C194  0.01uf, 6V3,DNI  [402]
C195  10uF  [3528T]
C196  100uF  [7343T]
C197  10uF  [3528T]
C198  100uF  [7343T]
FB5  0.1OHM1A  [SM-7351-IND-0805]
FB6  0.1OHM1A  [SM-7351-IND-0805]
FB9  0.1OHM1A  [SM-7351-IND-0805]
LS1  Speaker  [PIN2]
P6  HDR_14X2  [HDR_14X2]
P11  Header 3  [HDR1X3]
P12  Header 3  [HDR1X3]
P13  Header 3  [HDR1X3]
P15  Header 3  [HDR1X3]
P16  SJ3524-3.5mm  [jack_audio1]
P17  SJ3524-3.5mm  [jack_audio1]
P19  Header 3  [HDR1X3]
Q3  DMC56404  [SMini6-F3-B]  (parts A,B of 2)
R32  510R, 1%  [R0402]
R33  0R, 1%  [R0603]
R34  100K, 1%  [R0402]
R35  121, 1%  [R0402]
R36  54, 1%  [R0402]
R37  10k, 1%  [R0402]
R38  10k, 1%  [R0402]
R40  10k, 1%  [R0402]
R42  0R, 1%  [R0603]
R43  0R, 1%  [R0402]
R44  0R, 1%  [R0402]
R101  0R, 1%  [R0402]
R102  0R, 1%  [R0402]
R103  0R, 1%  [R0402]
R104  2.2K,1%  [R0402]
R105  330R, 1%  [R0402]
R106  0R, 1%  [R0402]
R107  0R, 1%  [R0402]
R108  0R, 1%  [R0402]
R109  0R, 1%  [R0402]
R240  0R, 1%  [R0603]
R241  0R, 1%,1206,baoxian  [R1206]
R242  0R, 1%,DNI  [R0603]
R243  0R, 1%,DNI  [R0603]
R244  0R, 1%,DNI  [R0603]
R245  0R, 1%,DNI  [R0603]
R246  0R, 1%,DNI  [R0603]
R247  0R, 1%  [R0603]
R248  0R, 1%  [R0603]
R249  0R, 1%  [R0603]
R250  0R, 1%  [R0603]
R251  0R, 1%  [R0603]
R252  0R, 1%  [R0603]
R253  0R, 1%  [R0603]
R254  0R, 1%  [R0603]
R255  0R, 1%  [R0603]
R256  0R, 1%  [R0603]
R259  0R, 1%  [R0603]
R260  0R, 1%  [R0603]
S4  KMR231GLFS  [SW4SMD_63X161LS]
S5  KMR231GLFS  [SW4SMD_63X161LS]
S7  KMR231GLFS  [SW4SMD_63X161LS]
TP36  TESTPT1  [tp1-8040]  (value not drawn)  (no BOM)
TP37  TESTPT1  [tp1-8040]  (value not drawn)  (no BOM)
U1  MAX3232E  [MAX3232EEA/SSOP16]
U3  MAX3232E  [MAX3232EEA/SSOP16]
U11  TLV320AIC3106  [TLV320AIC3106/QFN-48]
U17  SMF05CT1G  [SMF05CT1G/SC-88]
U18  LTC1117_3.3  [SOT223]
U19  LTC1117-ADJ  [SOT223]
Y5  ACTIVE-12MHz  [OSC4_61X65LS_79X98SMD]

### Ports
12MHZ (bidir), EHRPWM1B (bidir), GPIO0_7 (bidir), GPIO1_15, GPIO1_16, GPIO1_17, GPIO1_28 (bidir), GPIO3_19, GPIO3_21 (bidir), I2C1_SCL (bidir), I2C1_SDA (bidir), I2C2_SCL, I2C2_SDA, MMC1_CMD_BEEP (bidir), SPI1_CS0 (bidir), SPI1_D0 (bidir), SPI1_D1 (bidir), SPI1_SCLK (bidir), SYS_RESETn (bidir), UART0_RXD (bidir), UART0_TXD (bidir), UART1_RXD (bidir), UART1_TXD (bidir), UART2_RXD (bidir), UART2_TXD (bidir), UART4_RXD, UART4_TXD

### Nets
3V3_AUD: C180.1 C181.1 C185.1 C186.2 C187.1 C188.2 FB6.1 U11.16(DRVDD) U11.17(DRVDD) U11.24(DRVDD) U11.25(AVDD_DAC)
AGND_AUD: C180.2 C181.2 C182.2 C185.2 C186.1 C187.2 C188.1 C193.2 C194.2 FB9.1 P16.1 P17.1 U11.15(AVSS_ADC) U11.20(DRVSS) U11.21(DRVSS) U11.26(AVSS_DAC) U11.TPAD U17.2(GND) U17.5(A4)
DGND: C5.2 C126.1 C127.2 C128.2 C129.2 C145.2 C146.2 C148.2 C150.1 C151.2 C158.2 C174.2 C189.2 C190.1 C191.2 C192.1 C195.2 C196.2 C197.2 C198.2 FB9.2 P6.2 P6.4 P6.6 P6.23 P6.27 P11.3 P12.3 P13.3 P15.3 P19.3 Q3.1 R34.2 R36.2 S4.1(A1) S4.3(A3) S5.1(A1) S5.3(A3) S7.1(A1) S7.3(A3) U1.15(GND) U3.15(GND) U11.42(DVSS) U11.43(SELECT) U18.1(Adj/Gnd) Y5.2(GND)
PWR_ARM: P6.1 P6.3 P6.5 R241.2
VDD_1V8B: C191.1 C192.2 C198.1 R35.1 U11.36(DVDD) U19.2(Out)
VDD_3V3C: C126.2 C127.1 C150.2 C151.1 C189.1 C190.2 C196.1 FB6.2 R37.1 R38.1 R40.1 R43.2 U1.16(VCC) U3.16(VCC) U11.44(IOVDD) U11.45(MFP0) U11.46(MFP1) U18.2(Out) Y5.4(VCC)
VDD_5V: FB5.2
VDD_5V0: C5.1 C195.1 C197.1 FB5.1 R32.1 R241.1 U18.3(In) U19.3(In)
12MHZ: R103.1 ; port 12MHZ
AUD_HPLOUT: C178.2 U11.18(HPLOUT)
AUD_HPLOUT_JCK: C178.1 P16.2 U17.6(A5)
AUD_HPROUT: C177.2 U11.23(HPROUT)
AUD_HPROUT_JCK: C177.1 P16.4 U17.4(A3)
AUD_RESETn: R44.2 U11.33(RESETn)
COM1_RX: P6.9 R250.2
COM1_TX: P6.7 R248.2
COM2_RX: P6.10 R249.2
COM2_TX: P6.8 R247.2
EHRPWM1B: C148.1 R40.2 S7.2(A2) S7.4 ; port EHRPWM1B
FA_ARM_0: P6.12 R260.1
FA_ARM_1: P6.11 R253.2
FA_ARM_2: P6.14 R252.2
FA_ARM_3: P6.13 R251.2
FA_ARM_4: P6.16 R256.2
FA_ARM_5: P6.15 R255.2
GPIO0_7: C145.1 R37.2 S4.2(A2) S4.4 ; port GPIO0_7
GPIO1_15: R260.2 ; port GPIO1_15
GPIO1_16: R253.1 ; port GPIO1_16
GPIO1_17: R254.2 ; port GPIO1_17
GPIO1_28: C146.1 R38.2 S5.2(A2) S5.4 ; port GPIO1_28
GPIO3_19: R259.1 ; port GPIO3_19
GPIO3_21: R102.1 ; port GPIO3_21
I2C1_SCL: U11.1(SCL) ; port I2C1_SCL
I2C1_SDA: U11.2(SDA) ; port I2C1_SDA
I2C2_SCL: R251.1 ; port I2C2_SCL
I2C2_SDA: R255.1 ; port I2C2_SDA
MMC1_CMD_BEEP: Q3.2 R34.1 ; port MMC1_CMD_BEEP
OEM_RXD: P19.1 R246.1
OEM_TXD: P19.2 R245.1
RS232_0_RXD: P13.1 U3.13(RIN1)
RS232_0_TXD: P13.2 U3.14(DOUT1)
RS232_1_RXD: P11.1 R248.1 U1.8(RIN2)
RS232_1_TXD: P11.2 R250.1 U1.7(DOUT2)
RS232_2_RXD: P12.1 U1.13(RIN1)
RS232_2_TXD: P12.2 U1.14(DOUT1)
RS232_5_RXD: P15.1 U3.8(RIN2)
RS232_5_TXD: P15.2 U3.7(DOUT2)
RXN: P6.20
RXP: P6.19
SPI1_CS0: U11.41(DOUT) ; port SPI1_CS0
SPI1_D0: U11.39(WCLK) ; port SPI1_D0
SPI1_D1: U11.40(DIN) ; port SPI1_D1
SPI1_SCLK: U11.38(BCLK) ; port SPI1_SCLK
SYS_RESETn: R44.1 ; port SYS_RESETn
TCT_RCT: P6.21 P6.22
TXN: P6.18
TXP: P6.17
UART0_RXD: R42.1 ; port UART0_RXD
UART0_TXD: R240.1 ; port UART0_TXD
UART1_RXD: R244.1 ; port UART1_RXD
UART1_TXD: R243.1 ; port UART1_TXD
UART2_RXD: R33.1 R247.1 ; port UART2_RXD
UART2_TXD: R242.1 R249.1 ; port UART2_TXD
UART4_RXD: R256.1 ; port UART4_RXD
UART4_TXD: R252.1 ; port UART4_TXD
USB1_DM: P6.26
USB1_DP: P6.28
VBUS: P6.25
NetC128_1: C128.1 U1.2(V+)
NetC129_1: C129.1 U1.6(V-)
NetC130_1: C130.1 U1.1(C1+)
NetC130_2: C130.2 U1.3(C1-)
NetC144_1: C144.1 U1.4(C2+)
NetC144_2: C144.2 U1.5(C2-)
NetC158_1: C158.1 U3.2(V+)
NetC174_1: C174.1 U3.6(V-)
NetC175_1: C175.1 U3.1(C1+)
NetC175_2: C175.2 U3.3(C1-)
NetC176_1: C176.1 U3.4(C2+)
NetC176_2: C176.2 U3.5(C2-)
NetC179_1: C179.1 U11.11(MIC3L) U11.14(MIC3R)
NetC179_2: C179.2 R105.2 R106.2 R107.2
NetC182_1: C182.1 R104.2 R105.1
NetC183_1: C183.1 U11.3(LINE1LP)
NetC183_2: C183.2 R108.1
NetC184_1: C184.1 U11.5(LINE1RP)
NetC184_2: C184.2 R109.1
NetC193_1: C193.1 U11.6(LINE1RM)
NetC194_1: C194.1 U11.4(LINE1LM)
NetLS1_1: LS1.1 R32.2
NetLS1_2: LS1.2 Q3.6
NetP17_2: P17.2 R107.1 R108.2 U17.3(A2)
NetP17_4: P17.4 R106.1 R109.2 U17.1(A1)
NetR33_2: R33.2 U1.12(ROUT1)
NetR35_2: R35.2 R36.1 U19.1(Adj/Gnd)
NetR42_2: R42.2 U3.12(ROUT1)
NetR43_1: R43.1 Y5.1(OE)
NetR101_1: R101.1 R102.2 R103.2 U11.37(MCLK)
NetR101_2: R101.2 Y5.3(CLK)
NetR104_1: R104.1 U11.13(MICBIAS)
NetR240_2: R240.2 U3.11(DIN1)
NetR242_2: R242.2 U1.11(DIN1)
NetR243_2: R243.2 U1.10(DIN2)
NetR244_2: R244.2 U1.9(ROUT2)
NetR245_2: R245.2 U3.10(DIN2)
NetR246_2: R246.2 U3.9(ROUT2)
NetR254_1: R254.1 TP36.1(TP)
NetR259_2: R259.2 TP37.1(TP)

Not connected (* = marked no-connect by the designer): P6 24*; P16 3* 5*; P17 3* 5*; Q3 3* 4* 5*; U11 7(LINE2LP) 8(LINE2LM) 9(LINE2RP) 10(LINE2RM) 12(MICDET)* 19(HPLCOM)* 22(HPRCOM)* 27(MONO_LOP) 28(MONO_LOM) 29(LEFT_LOP) 30(LEFT_LOM) 31(RIGHT_ROP) 32(RIGHT_ROM) 34(GPIO2)* 35(GPIO1)* 47(MFP2)* 48(MFP3)*

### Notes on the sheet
- (near C195) Yang
- (near C196) Yang
- (near C197) Yang
- (near C198) Yang
- (near R241) Yang

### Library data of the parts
C5 C195-C198 = CAPACITOR POL: Capacitor
C126 C150 C181 C186 C188 C190 C192 = CAP_10uF_Y5V_10V_10%_0805: as C204-C206 on sheet P10_LCD
C127-C130 C144-C146 C148 C151 C158 C174-C176 C179 C180 C182-C185 C187 C189 C191 C193 C194 = CAP_0.1uF_X7R_16V_10% 0402: as C131 on sheet P09_Ethernet
C177 C178 = Cap: Capacitor
FB5 FB6 FB9 = FER_180_200_0: as FB12-FB17 on sheet P10_LCD
LS1 = Speaker: Loudspeaker
P11-P13 P15 P19 = Header 3: Header, 3-Pin
Q3 = RN1907: TRANS PREBIASED DUAL NPN SOT363; Manufacturer: Toshiba; Manufacturer Part Number: DDC114YU-7-F; Order# 2: BCR135S; ATLStockNo1: 2130.0137; ATLStockNo2: 2130.01; Transistor Type: 2 NPN - Pre-Biased (Dual); Current - Collector (Ic) (Max): 100mA; Voltage - Collector Emitter Breakdown (Max): 50V; Resistor - Base (R1) (Ohms): 10k; Resistor - Emitter Base (R2) (Ohms): 47k; DC Current Gain (hFE) (Min) @ Ic, Vce: 68 @ 10mA, 5V; Vce Saturation (Max) @ Ib, Ic: 300mV @ 250µA, 5mA; Current - Collector Cutoff (Max): 500nA; Frequency - Transition: 250MHz; Power - Max: 200mW
R32 R34 = RES_100K_1/16W_1%_0402: RES 100K OHM 1/16W 1% 0402 SMD; Manufacturer: Stackpole Electronics Inc; Manufacturer Part Number: RMCF0402FT100K; Power (Watts): 0.063W, 1/16W; Temperature Coefficient: ?00ppm/°C; Tolerance: ?%
R33 R42-R44 R101-R109 R240 = RES_0_1/16W_1%_0402: RES 0.0 OHM 1/16W 0402 SMD; Manufacturer: Yageo; Manufacturer Part Number: RC0402JR-070RL; Resistance (Ohms): 0.0; Power (Watts): 0.063W, 1/16W; Tolerance: Jumper
R35-R38 R40 = RES_10K_1/16W_1%_0402: as R96 on sheet P07_DDR3_SDRAM
R241 = RES_470_1/10W_5%_0402: as R149 on sheet P10_LCD
R242-R245 = RES_0_1/16W_1%_0402: RES 0.0 OHM,0603; Manufacturer: Yageo; Manufacturer Part Number: RC0402JR-070RL; Resistance (Ohms): 0.0; Power (Watts): 0.063W, 1/16W; Tolerance: Jumper
R246-R256 R259 R260 = RES_0_1/16W_1%_0402: RES 0.0 OHM,0603,DNI; Manufacturer: Yageo; Manufacturer Part Number: RC0402JR-070RL; Resistance (Ohms): 0.0; Power (Watts): 0.063W, 1/16W; Tolerance: Jumper
S4 S5 S7 = KMR2: Microminiature Tact Switch for SMT; Manufacturer: C&K Components; Circuit: SPST-NO; Switch Function: Off-Mom; Contact Rating @ Voltage: 0.05A @ 32VDC; Actuator Type: Standard; Actuator Height off PCB, from Pins: 1.90mm; Actuator Orientation: Top Actuated; Outline: 4.60mm x 2.80mm; Illumination: Non-Illuminated; Operating Force: 300gf; Switch Travel: 0.25mm; Mechanical Life: 150,000 Cycles
U18 U19 = AMS1117_X
Y5 = ASDMB: Manufacturer: Abracon Corporation; Manufacturer Part Number: ASDMB-24.576MHZ-LC-T; Frequency: 24.576MHz; Function: Standby (Power Down); Output: CMOS; Voltage - Supply: 1.8 V ~ 3.3 V; Frequency Stability: ?0ppm; Current - Supply (Max): 16mA; Current - Supply (Disable) (Max): 15µA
